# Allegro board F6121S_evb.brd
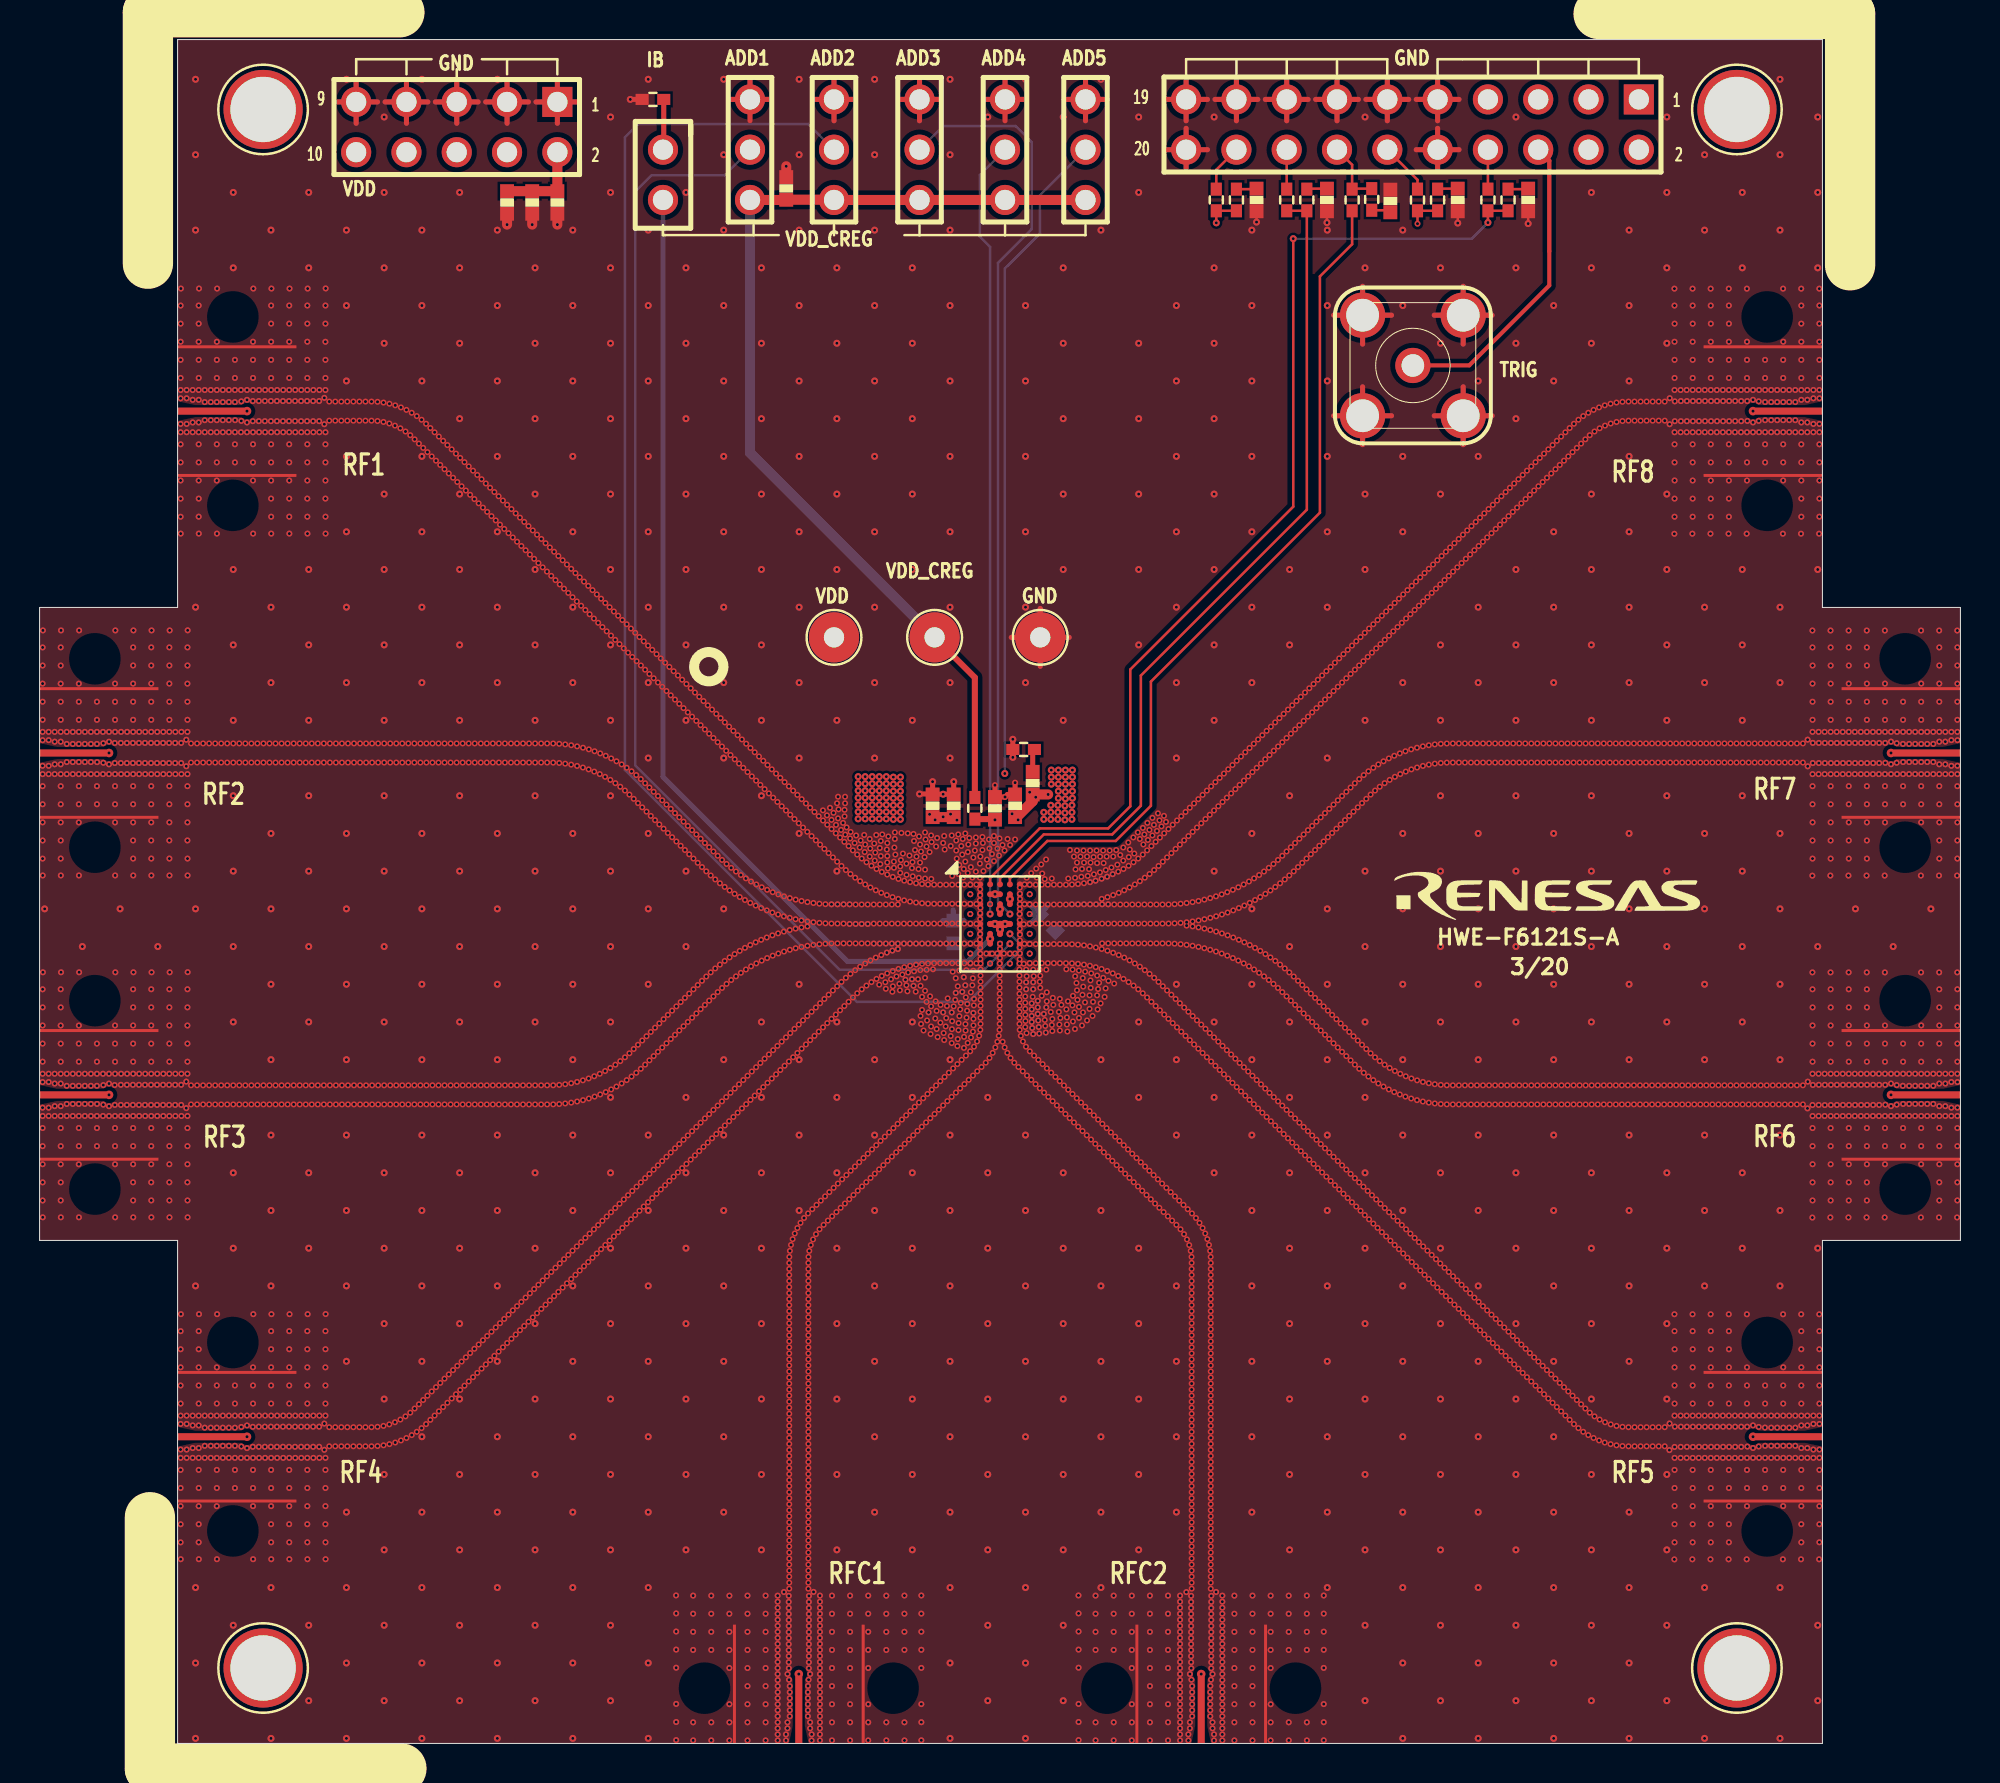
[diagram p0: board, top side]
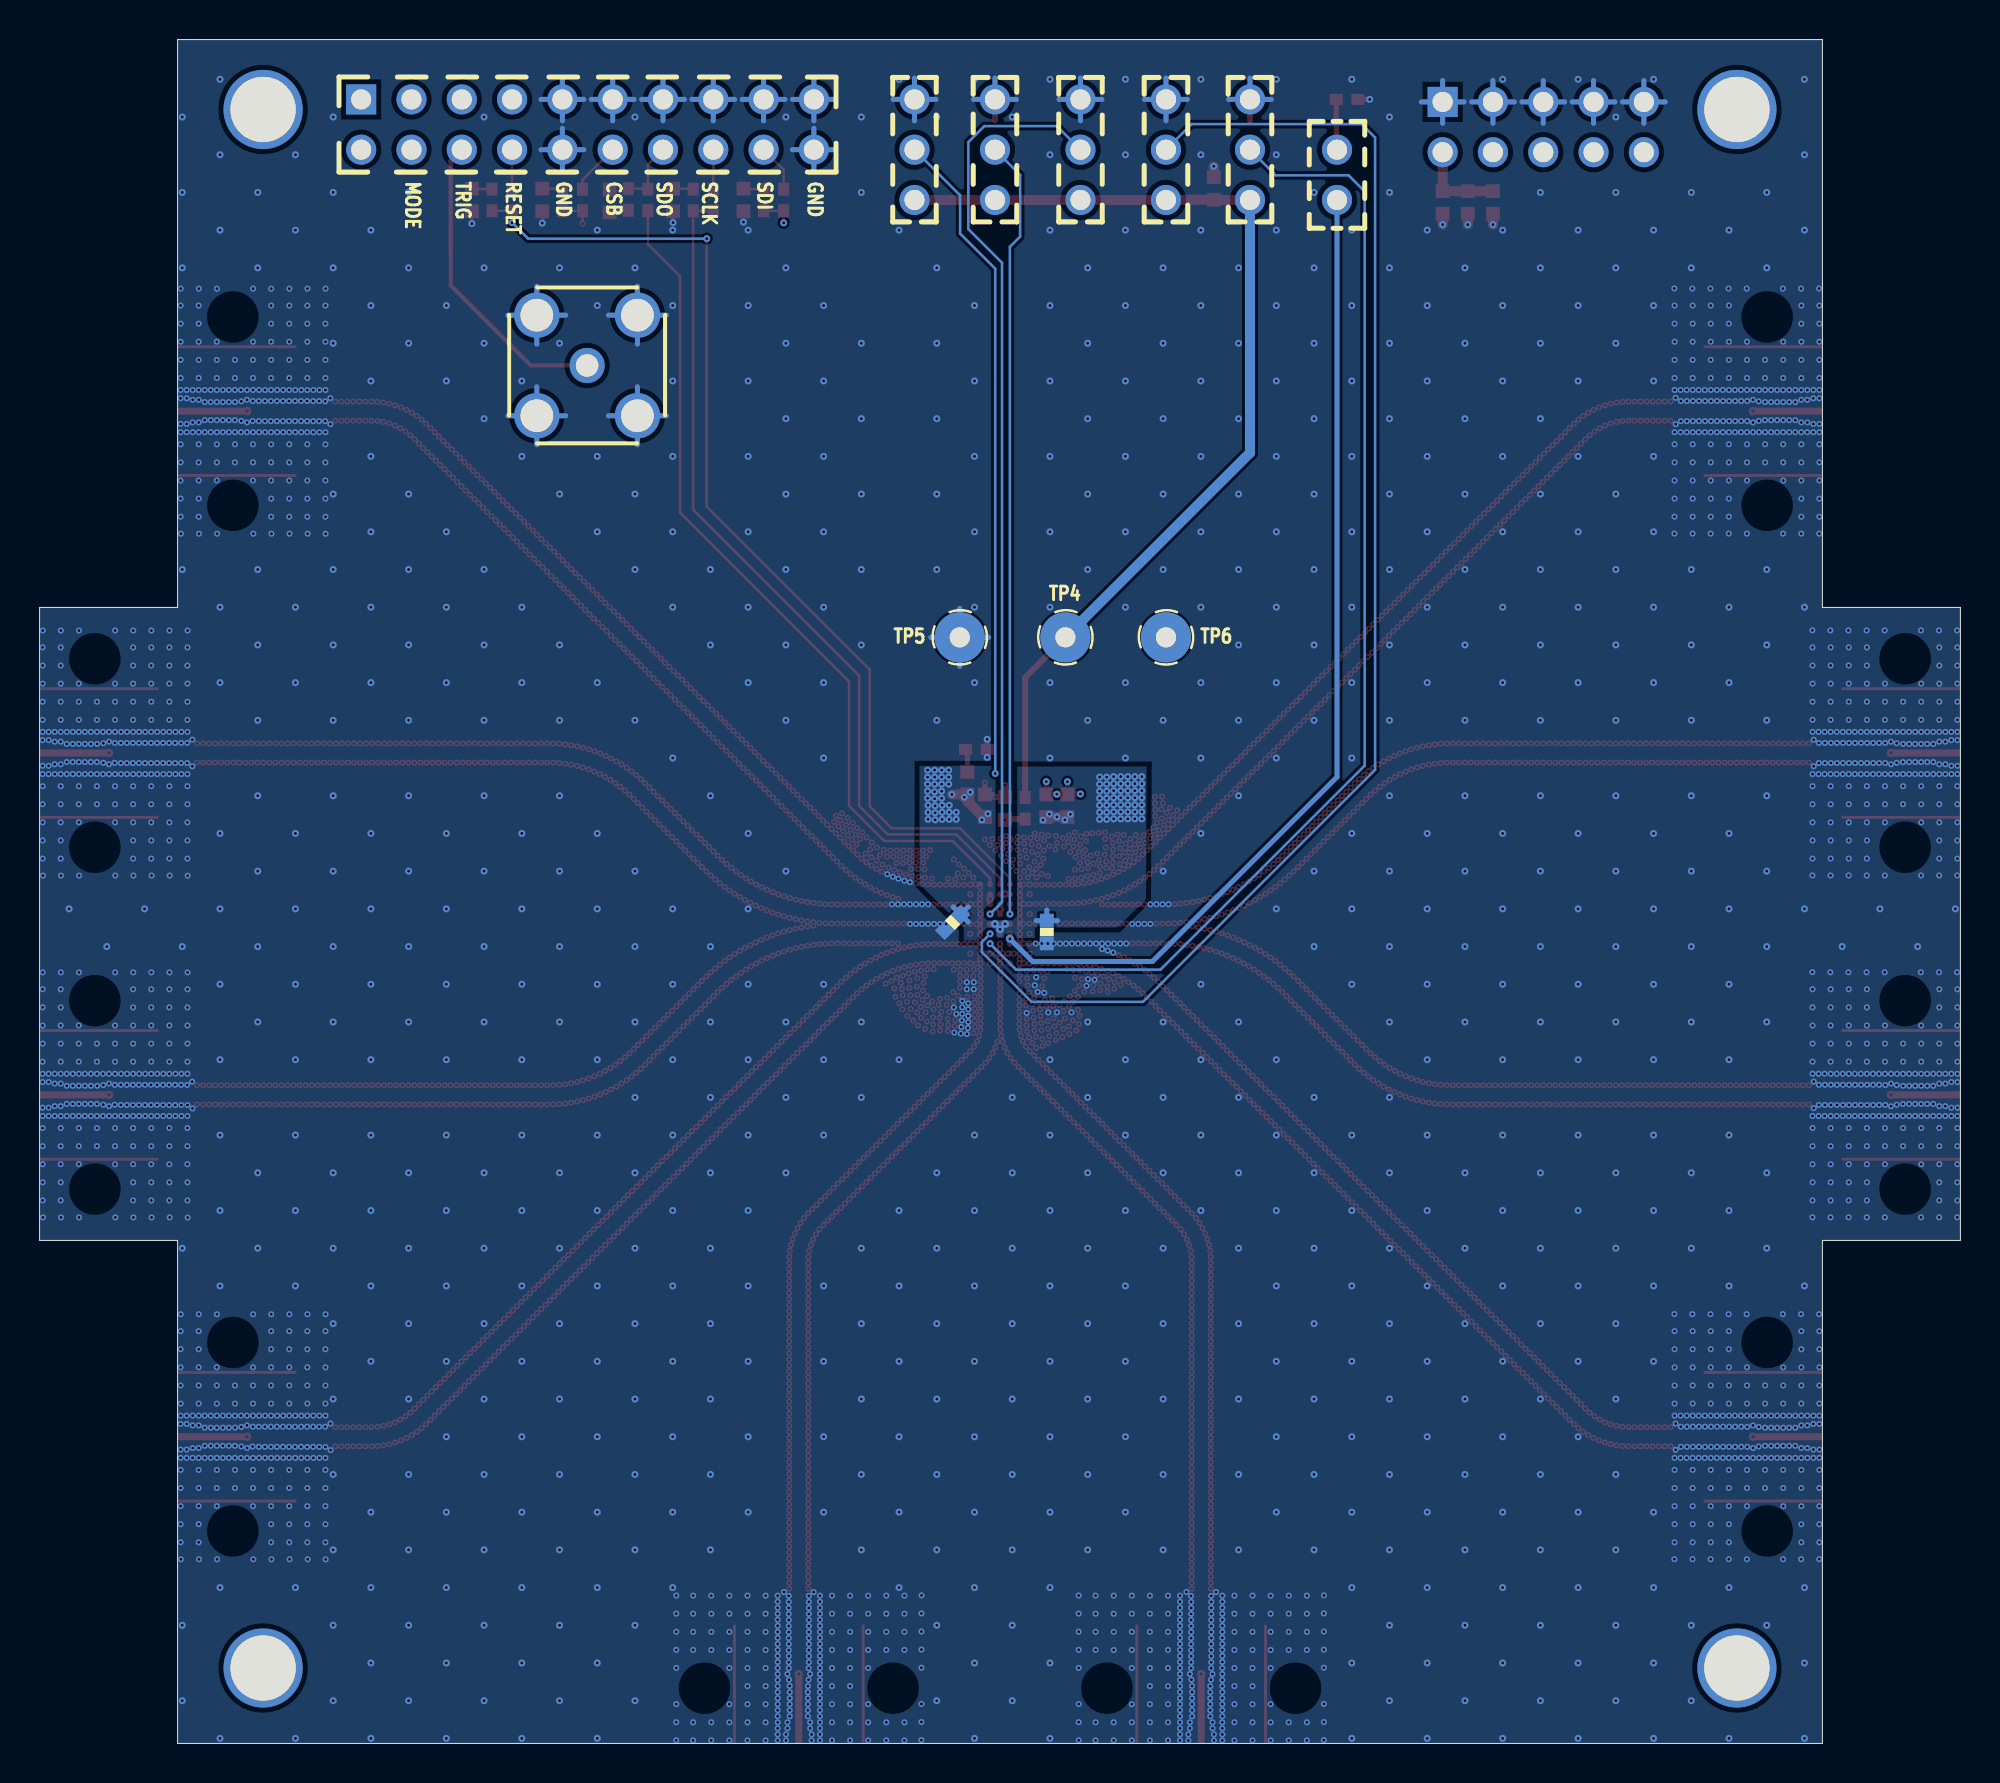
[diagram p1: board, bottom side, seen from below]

Outline 96.99 x 86.08 mm; copper layers: TOP, L2, L3, BOTTOM. Coordinates in mm from the lower left corner of the outline.
Outline path: 0,57.39 0,25.41 6.97,25.41 6.97,0 90.03,0 90.03,25.41 96.99,25.41 96.99,57.39 90.03,57.39 90.03,86.08 6.97,86.08 6.97,57.39 0,57.39

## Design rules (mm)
constraint set DEFAULT: min track width 0.127

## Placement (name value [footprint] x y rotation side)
C1  10uF  [CAPC1005N]  26.14 77.85 90 top
C3  DNI_C0402  [CAPC1005N]  23.6 77.85 90 top
C4  1uF  [CAPC1005N]  24.87 77.85 90 top
C5  100pF  [CAPC1005N]  46.16 47.37 270 top
C6  100pF  [CAPC1005N]  49.26 47.37 270 top
C7  0.1uF  [CAPC1005N]  45.09 47.37 270 top
C8  1uF  [CAPC1005N]  37.7 78.56 270 top
C9  1uF  [CAPC1005N]  48.24 47.24 90 top
C12  DNI_C0402  [CAPC1005N]  75.17 77.98 90 top
C14  DNI_C0402  [CAPC1005N]  71.61 77.98 90 top
C15  DNI_C0402  [CAPC1005N]  65.01 77.98 90 top
C16  DNI_C0402  [CAPC1005N]  61.45 77.98 90 top
C17  DNI_C0402  [CAPC1005N]  68.21 77.93 270 top
C18  0.018uF  [CAPC1005N]  50.88 41.48 135 bottom
C19  3900pF  [CAPC1005N]  46.13 41 90 bottom
C20  0.068uF  [CAPC1005N]  50.15 48.51 270 top
FID1  Fiducial  [FIDUCIAL]  91.42 87.38 0 top
FID2  Fiducial  [FIDUCIAL]  5.57 -1.27 180 top
FID3  Fiducial  [FIDUCIAL]  5.47 87.46 90 top
J1  ELF40-002 F6212  [ELF40-002_F6121]  6.97 67.31 270 top
J2  ELF40-002 F6212  [ELF40-002_F6121]  0 50.04 270 top
J3  ELF40-002 F6212  [ELF40-002_F6121]  0 32.77 270 top
J4  ELF40-002 F6212  [ELF40-002_F6121]  6.97 15.49 270 top
J5  ELF40-002 F6212  [ELF40-002_F6121]  38.34 0 0 top
J10  ELF40-002 F6212  [ELF40-002_F6121]  58.66 0 0 top
J11  Headerstrip 1X3  [HEADER_1X3_VERTICAL]  35.87 80.52 270 top
J12  Headerstrip 1X3  [HEADER_1X3_VERTICAL]  40.11 80.52 90 top
J13  Headerstrip 1X3  [HEADER_1X3_VERTICAL]  44.43 80.52 90 top
J14  Headerstrip 1X3  [HEADER_1X3_VERTICAL]  48.75 80.52 90 top
J15  Headerstrip 1X3  [HEADER_1X3_VERTICAL]  52.81 80.52 270 top
J16  Headerstrip 2X5  [HEADER_2X5]  21.06 81.66 180 top
J17  ELF40-002 F6212  [ELF40-002_F6121]  90.03 15.49 90 top
J18  ELF40-002 F6212  [ELF40-002_F6121]  96.99 32.77 90 top
J19  ELF40-002 F6212  [ELF40-002_F6121]  96.99 50.04 90 top
J20  ELF40-002 F6212  [ELF40-002_F6121]  90.03 67.31 90 top
J22  Headerstrip 2X10  [HEADER_2X10]  69.32 81.79 180 top
J23  Headerstrip 1X2  [HEADER_1X2_VERTICAL]  31.48 79.25 270 top
J30  TE: 1-1337482-0  [SMA_VERT_SNAP_ON-5]  69.35 69.62 0 top
NOREF  -  []  68.05 41.4 0 top
NOREF#2  -  []  -216.17 -221.64 0 top
NOREF#3  -  []  6.97 0 90 top
NOREF#4  -  []  6.97 86.08 0 top
R10  0.00  [RESC1005N]  73.13 77.98 270 top
R11  DNI_R0402  [RESC1005N]  74.15 77.98 270 top
R12  0.00  [RESC1005N]  69.58 77.98 270 top
R13  DNI_R0402  [RESC1005N]  70.59 77.98 270 top
R14  0.00  [RESC1005N]  62.97 77.98 270 top
R15  DNI_R0402  [RESC1005N]  63.99 77.98 270 top
R16  0.00  [RESC1005N]  59.42 77.98 270 top
R17  DNI_R0402  [RESC1005N]  60.43 77.98 270 top
R18  0.00  [RESC1005N]  66.28 77.98 270 top
R19  DNI_R0402  [RESC1005N]  67.27 78 90 top
R20  DNI_R0402  [RESC1005N]  47.23 47.24 90 top
R21  DNI_R0402  [RESC1005N]  30.97 83.06 180 top
R26  0.00  [RESC1005N]  49.69 50.22 0 top
SO1  Standoff 25mm  [MH320]  11.29 82.55 0 top
SO2  Standoff 25mm  [MH320]  85.71 82.55 0 top
SO3  Standoff 25mm  [MH320]  11.29 3.81 0 top
SO4  Standoff 25mm  [MH320]  85.71 3.81 0 top
TP4  Loop  [TP254_102]  45.19 55.88 0 top
TP5  Loop  [TP254_102]  50.53 55.88 0 top
TP6  Loop  [TP254_102]  40.11 55.88 0 top
U3  F6121S  [BGA63_50P_3X4]  48.5 41.4 0 top

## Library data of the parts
C1 C3-C9 C12 C14-C20 = CAP_1005N: alternate symbols: (CAPC1005L,CAPC1005RF)
FID1-FID3 = Fiducial
J1-J5 J10 J17-J20 = SMA_EDGE_ELF40
J11-J15 = HEADER_1X3
J16 = HEADER_2X5
J22 = HEADER_2X10
J23 = header_1x2
J30 = SMA_VERT_SNAPON
R10-R21 R26 = RESISTOR_1005N: alternate symbols: (RESC1005RF,RESC1005L,RESC1005M)
SO1-SO4 = Standoff
TP4-TP6 = TESTPOINT
U3 = F6121S

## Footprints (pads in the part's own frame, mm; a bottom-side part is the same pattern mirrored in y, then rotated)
BGA63_50P_3X4
  round 0.3 smd: A1(-1.5,2) A2(-1,2) A3(-0.5,2) A4(0,2) A5(0.5,2) A6(1,2) A7(1.5,2) B1(-1.5,1.5) B2(-1,1.5) B3(-0.5,1.5) B4(0,1.5) B5(0.5,1.5) B6(1,1.5) B7(1.5,1.5) C1(-1.5,1) C2(-1,1) C3(-0.5,1) C4(0,1) C5(0.5,1) C6(1,1) C7(1.5,1) D1(-1.5,0.5) D2(-1,0.5) D3(-0.5,0.5) D4(0,0.5) D5(0.5,0.5) D6(1,0.5) D7(1.5,0.5) E1(-1.5,0) E2(-1,0) E3(-0.5,0) E4(0,0) E5(0.5,0) E6(1,0) E7(1.5,0) F1(-1.5,-0.5) F2(-1,-0.5) F3(-0.5,-0.5) F4(0,-0.5) F5(0.5,-0.5) F6(1,-0.5) F7(1.5,-0.5) G1(-1.5,-1) G2(-1,-1) G3(-0.5,-1) G4(0,-1) G5(0.5,-1) G6(1,-1) G7(1.5,-1) H1(-1.5,-1.5) H2(-1,-1.5) H3(-0.5,-1.5) H4(0,-1.5) H5(0.5,-1.5) H6(1,-1.5) H7(1.5,-1.5) J1(-1.5,-2) J2(-1,-2) J3(-0.5,-2) J4(0,-2) J5(0.5,-2) J6(1,-2) J7(1.5,-2)
CAPC1005N
  rect 0.7x0.7 smd: 1(-0.572,0) 2(0.572,0)
ELF40-002_F6121
  round 0 hole 2.032 unplated: (-4.76,2.79) (4.76,2.79)
  rect 0.15x2.54 smd: 1(0,1.27)
  rect 0.15x6 smd: 2(3.25,3) 3(-3.25,3)
HEADER_1X2_VERTICAL
  round 1.52 hole 1.02: 1(-1.27,0) 2(1.27,0)
HEADER_1X3_VERTICAL
  round 1.52 hole 1.02: 1(-2.54,0) 2(0,0) 3(2.54,0)
HEADER_2X5
  rect 1.52x1.52 hole 1.02: 1(-5.08,-1.27)
  round 1.52 hole 1.02: 2(-5.08,1.27) 3(-2.54,-1.27) 4(-2.54,1.27) 5(0,-1.27) 6(0,1.27) 7(2.54,-1.27) 8(2.54,1.27) 9(5.08,-1.27) 10(5.08,1.27)
HEADER_2X10
  rect 1.52x1.52 hole 1.02: 1(-11.43,-1.27)
  round 1.52 hole 1.02: 2(-11.43,1.27) 3(-8.89,-1.27) 4(-8.89,1.27) 5(-6.35,-1.27) 6(-6.35,1.27) 7(-3.81,-1.27) 8(-3.81,1.27) 9(-1.27,-1.27) 10(-1.27,1.27) 11(1.27,-1.27) 12(1.27,1.27) 13(3.81,-1.27) 14(3.81,1.27) 15(6.35,-1.27) 16(6.35,1.27) 17(8.89,-1.27) 18(8.89,1.27) 19(11.43,-1.27) 20(11.43,1.27)
MH320
  round 4 hole 3.3: (0,0)
RESC1005N
  rect 0.66x0.56 smd: 1(-0.546,0) 2(0.546,0)
SMA_VERT_SNAP_ON-5
  round 1.778 hole 1.143: 1(0,0)
  round 2.286 hole 1.651: 2(-2.54,2.54) 3(2.54,2.54) 4(2.54,-2.54) 5(-2.54,-2.54)
TP254_102
  round 2.54 hole 1.02: 1(0,0)

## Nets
GND: C1.1 C3.1 C4.1 C5.1 C6.1 C7.1 C8.1 C9.2(B) C12.1 C14.1 C15.1 C16.1 C17.1 C18.1 C19.1 J1.2 J1.3 J2.2 J2.3 J3.2 J3.3 J4.2 J4.3 J5.2 J5.3 J10.2 J10.3 J11.1 J12.3 J13.3 J14.3 J15.1 J16.1 J16.3 J16.5 J16.7 J16.9 J17.2 J17.3 J18.2 J18.3 J19.2 J19.3 J20.2 J20.3 J22.9 J22.10 J22.11 J22.13 J22.15 J22.17 J22.19 J22.20 J30.2 J30.3 J30.4 J30.5 R21.2 R26.1 TP5.1 U3.A1 U3.A2 U3.A6 U3.A7 U3.B2 U3.B6 U3.C1 U3.C2 U3.C6 U3.C7 U3.D2 U3.D6 U3.E1 U3.E2 U3.E6 U3.E7 U3.F2 U3.F6 U3.G1 U3.G2 U3.G4 U3.G6 U3.G7 U3.H2 U3.H3 U3.H4 U3.H5 U3.H6 U3.J1 U3.J2 U3.J4 U3.J6 U3.J7
VDD: C1.2(B) C3.2(B) C4.2(B) C5.2(B) C6.2(B) C7.2(B) C18.2(B) C19.2(B) C20.2(B) J16.2 J16.4 J16.6 J16.8 J16.10 TP6.1 U3.E3 U3.E4 U3.E5 U3.F4(VDD_F4)
VDD_CREG: C8.2(B) J11.3 J12.1 J13.1 J14.1 J15.3 R20.2 TP4.1
ADD1: J11.2 U3.G5
ADD2: J12.2 U3.F5
ADD3: J13.2 U3.D5
ADD4: J14.2 U3.D3
ADD5: J15.2 U3.C3
CREG: C9.1 R20.1 U3.C4 U3.D4
CSB: R12.2 R13.2 U3.B3 U3.B4
F2232H_CSB: J22.12 R12.1
F2232H_RESET: J22.8 R10.1
F2232H_SCLK: J22.16 R14.1
RESET: R10.2 R11.2 U3.A3
RF1: J1.1 U3.B1
RF2: J2.1 U3.D1
RF3: J3.1 U3.F1
RF4: J4.1 U3.H1
RF5: J17.1 U3.H7
RF6: J18.1 U3.F7
RF7: J19.1 U3.D7
RF8: J20.1 U3.B7
SCLK: R14.2 R15.2 U3.A4
SDI: R16.2 R17.2 U3.B5 U3.C5
SDO: R18.2 U3.A5
TRIG: J22.6 J30.1(S1)
N397655: J10.1 U3.J5
N397670: J5.1 U3.J3
N472884: C12.2(B) R11.1
N475952: J22.18 R16.1
N485360: J22.14 R18.1 R19.2
N489259: J23.1 R21.1
N510107: C14.2(B) R13.1
N511327: C17.2(B) R19.1
N512531: C15.2(B) R15.1
N513256: C16.2(B) R17.1
N546379: J23.2 U3.F3 U3.G3
N558773: C20.1 R26.2

Pads without a net: J22 1 2 3 4 5 7

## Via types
v1: diameter 0.305, hole 0.152, TOP to L2, 387 vias
v2: diameter 0.406, hole 0.152, TOP to BOTTOM, 4 vias
v3: diameter 0.305, hole 0.152, TOP to L3, 2573 vias
v4: diameter 0.406, hole 0.152, TOP to L3, 1 via
v5: diameter 0.406, hole 0.152, TOP to L2, 2 vias
v6: diameter 0.356, hole 0.152, TOP to BOTTOM, 829 vias
v7: diameter 0.305, hole 0.152, TOP to BOTTOM, 2008 vias

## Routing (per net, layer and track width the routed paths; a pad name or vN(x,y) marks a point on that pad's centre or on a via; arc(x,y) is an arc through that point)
GND: length 429.3
  TOP w0.127: C12.1 v6(75.17,76.78) ; 45.11,47.96 C7.1 ; C14.1 v6(71.61,76.81) ; C16.1 v6(61.45,76.86) ; C15.1 v6(65.01,76.84)
  TOP w0.254: 21.06,81.85 J16.5 ; J16.5 19.99,82.93 ; J16.5 22.14,82.93 ; J16.5 21.06,84.01 ; 60.43,81.98 J22.17 ; J22.17 60.43,84.14 ; J22.17 59.36,83.06 ; J22.17 61.51,83.06 ; TP5.1 50.53,57.34 ; TP5.1 51.99,55.88 ; TP5.1 49.07,55.88 ; TP5.1 50.53,54.42 ; J22.19 58.97,83.06 ; J22.19 57.89,84.14 ; J22.19 56.82,83.06 ; J22.19 57.89,81.98 ; J30.4 73.35,67.08 ; J30.4 70.43,67.08 ; J30.4 71.89,68.54 ; J30.4 71.89,65.62 ; 70.43,72.16 J30.3 ; J30.3 71.89,73.62 ; J30.3 71.89,70.7 ; J30.3 73.35,72.16 ; 44.43,81.98 J13.3 ; J13.3 43.35,83.06 ; J13.3 44.43,84.14 ; J13.3 45.51,83.06 ; v3(48.24,48.41) C9.2 v3(48.75,47.82) 48.88,47.94 C6.1 v3(49.26,48.54) ; J22.11 69.13,83.06 ; J22.11 66.98,83.06 ; J22.11 68.05,84.14 ; J22.11 68.05,81.98 ; J11.1 35.87,84.14 ; J11.1 36.95,83.06 ; J11.1 34.79,83.06 ; J11.1 35.87,81.98 ; 25.07,82.93 J16.1 ; J16.1 26.14,81.85 ; J16.1 26.14,84.01 ; J16.1 27.22,82.93 ; 66.81,70.7 J30.2 ; J30.2 68.27,72.16 ; J30.2 65.35,72.16 ; J30.2 66.81,73.62 ; J16.3 24.68,82.93 ; J16.3 22.53,82.93 ; J16.3 23.6,81.85 ; J16.3 23.6,84.01 ; J14.3 48.75,84.14 ; J14.3 47.67,83.06 ; J14.3 49.83,83.06 ; J14.3 48.75,81.98 ; J22.13 66.59,83.06 ; J22.13 65.51,81.98 ; J22.13 65.51,84.14 ; J22.13 64.44,83.06 ; 14.91,82.93 J16.9 ; J16.9 15.98,84.01 ; J16.9 15.98,81.85 ; J16.9 17.06,82.93 ; J12.3 40.11,84.14 ; J12.3 39.04,83.06 ; J12.3 40.11,81.98 ; J12.3 41.19,83.06 ; J15.1 52.81,84.14 ; J15.1 53.89,83.06 ; J15.1 52.81,81.98 ; J15.1 51.74,83.06 ; 69.52,80.52 J22.10 ; J22.10 71.67,80.52 ; J22.10 70.59,81.6 ; J22.10 70.59,79.44 ; J16.7 19.6,82.93 ; J16.7 18.52,84.01 ; J16.7 18.52,81.85 ; J16.7 17.45,82.93 ; J22.9 70.59,84.14 ; J22.9 69.52,83.06 ; J22.9 71.67,83.06 ; J22.9 70.59,81.98 ; R21.2 v6(29.83,83.06) ; 56.82,80.52 J22.20 ; J22.20 58.97,80.52 ; J22.20 57.89,79.44 ; J22.20 57.89,81.6 ; v6(49.14,49.82) R26.1 v6(49.14,50.73) ; 45.11,47.96 v6(45.63,47.96) 46.15,47.96 C5.1 v6(46.16,48.59) ; J30.5 68.27,67.08 ; J30.5 66.81,65.62 ; J30.5 66.81,68.54 ; J30.5 65.35,67.08 ; 61.9,83.06 J22.15 ; J22.15 64.05,83.06 ; J22.15 62.97,84.14 ; J22.15 62.97,81.98 ; v6(45.09,48.59) C7.1 45.07,47.97 v6(44.43,47.97)
  TOP w0.508: C1.1 v6(26.14,76.73) ; C3.1 v6(23.6,76.73) ; C4.1 v6(24.87,76.73) ; C8.1 v6(37.7,79.68)
  L2 w0.254: 40.11,81.98 J12.3 ; J12.3 40.11,84.14 ; J12.3 39.04,83.06 ; J12.3 41.19,83.06 ; 68.05,81.98 J22.11 ; J22.11 66.98,83.06 ; J22.11 69.13,83.06 ; J22.11 68.05,84.14 ; 57.89,79.44 J22.20 ; J22.20 58.97,80.52 ; J22.20 56.82,80.52 ; J22.20 57.89,81.6 ; 70.43,67.08 J30.4 ; J30.4 71.89,65.62 ; J30.4 71.89,68.54 ; J30.4 73.35,67.08 ; 34.79,83.06 J11.1 ; J11.1 36.95,83.06 ; J11.1 35.87,81.98 ; J11.1 35.87,84.14 ; 52.81,81.98 J15.1 ; J15.1 51.74,83.06 ; J15.1 52.81,84.14 ; J15.1 53.89,83.06 ; 65.35,67.08 J30.5 ; J30.5 66.81,68.54 ; J30.5 68.27,67.08 ; J30.5 66.81,65.62 ; J13.3 44.43,84.14 ; J13.3 43.35,83.06 ; J13.3 44.43,81.98 ; J13.3 45.51,83.06 ; J22.10 71.67,80.52 ; J22.10 70.59,81.6 ; J22.10 70.59,79.44 ; J22.10 69.52,80.52 ; J22.13 65.51,84.14 ; J22.13 66.59,83.06 ; J22.13 64.44,83.06 ; J22.13 65.51,81.98 ; 57.89,81.98 J22.19 ; J22.19 56.82,83.06 ; J22.19 58.97,83.06 ; J22.19 57.89,84.14 ; J16.9 17.06,82.93 ; J16.9 14.91,82.93 ; J16.9 15.98,84.01 ; J16.7 18.52,84.01 ; J16.7 19.6,82.93 ; J16.7 17.45,82.93 ; J16.5 22.14,82.93 ; J16.5 21.06,84.01 ; J16.5 19.99,82.93 ; J30.3 73.35,72.16 ; J30.3 70.43,72.16 ; J30.3 71.89,70.7 ; J30.3 71.89,73.62 ; J14.3 49.83,83.06 ; J14.3 48.75,81.98 ; J14.3 48.75,84.14 ; J14.3 47.67,83.06 ; 65.35,72.16 J30.2 ; J30.2 66.81,73.62 ; J30.2 66.81,70.7 ; J30.2 68.27,72.16 ; TP5.1 50.53,57.07 ; TP5.1 49.34,55.88 ; TP5.1 51.72,55.88 ; TP5.1 50.53,54.69 ; J22.17 61.51,83.06 ; J22.17 60.43,84.14 ; J22.17 59.36,83.06 ; J22.17 60.43,81.98 ; 70.59,81.98 J22.9 ; J22.9 70.59,84.14 ; J22.9 71.67,83.06 ; J22.9 69.52,83.06 ; 61.9,83.06 J22.15 ; J22.15 62.97,81.98 ; J22.15 64.05,83.06 ; J22.15 62.97,84.14 ; J16.3 23.6,84.01 ; J16.3 24.68,82.93 ; J16.3 22.53,82.93 ; J16.1 26.14,84.01 ; J16.1 27.22,82.93 ; J16.1 25.07,82.93
  L3 w0.254: J22.13 65.51,84.14 ; J22.13 64.44,83.06 ; J22.13 65.51,81.98 ; J22.13 66.59,83.06 ; J16.1 27.22,82.93 ; J16.1 26.14,84.01 ; J16.1 26.14,81.85 ; J16.1 25.07,82.93 ; J30.3 71.89,73.62 ; J30.3 71.89,70.7 ; J30.3 70.43,72.16 ; J30.3 73.35,72.16 ; J16.9 15.98,84.01 ; J16.9 15.98,81.85 ; J16.9 14.91,82.93 ; J16.9 17.06,82.93 ; 62.97,81.98 J22.15 ; J22.15 61.9,83.06 ; J22.15 62.97,84.14 ; J22.15 64.05,83.06 ; 49.34,55.88 TP5.1 ; TP5.1 50.53,57.07 ; TP5.1 50.53,54.69 ; TP5.1 51.72,55.88 ; 52.81,81.98 J15.1 ; J15.1 52.81,84.14 ; J15.1 51.74,83.06 ; J15.1 53.89,83.06 ; J30.5 68.27,67.08 ; J30.5 65.35,67.08 ; J30.5 66.81,65.62 ; J30.5 66.81,68.54 ; 17.45,82.93 J16.7 ; J16.7 19.6,82.93 ; J16.7 18.52,84.01 ; J16.7 18.52,81.85 ; J22.20 58.97,80.52 ; J22.20 57.89,79.44 ; J22.20 56.82,80.52 ; J22.20 57.89,81.6 ; J14.3 48.75,84.14 ; J14.3 49.83,83.06 ; J14.3 48.75,81.98 ; J14.3 47.67,83.06 ; 44.43,81.98 J13.3 ; J13.3 45.51,83.06 ; J13.3 43.35,83.06 ; J13.3 44.43,84.14 ; J22.19 58.97,83.06 ; J22.19 57.89,84.14 ; J22.19 57.89,81.98 ; J22.19 56.82,83.06 ; J12.3 40.11,84.14 ; J12.3 41.19,83.06 ; J12.3 39.04,83.06 ; J12.3 40.11,81.98 ; 65.35,72.16 J30.2 ; J30.2 68.27,72.16 ; J30.2 66.81,70.7 ; J30.2 66.81,73.62 ; 19.99,82.93 J16.5 ; J16.5 21.06,84.01 ; J16.5 22.14,82.93 ; J16.5 21.06,81.85 ; J22.17 61.51,83.06 ; J22.17 60.43,81.98 ; J22.17 59.36,83.06 ; J22.17 60.43,84.14 ; J22.10 71.67,80.52 ; J22.10 69.52,80.52 ; J22.10 70.59,79.44 ; J22.10 70.59,81.6 ; J16.3 23.6,84.01 ; J16.3 24.68,82.93 ; J16.3 22.53,82.93 ; J16.3 23.6,81.85 ; 70.43,67.08 J30.4 ; J30.4 71.89,68.54 ; J30.4 73.35,67.08 ; J30.4 71.89,65.62 ; 35.87,81.98 J11.1 ; J11.1 34.79,83.06 ; J11.1 35.87,84.14 ; J11.1 36.95,83.06 ; J22.9 70.59,84.14 ; J22.9 71.67,83.06 ; J22.9 70.59,81.98 ; J22.9 69.52,83.06 ; 66.98,83.06 J22.11 ; J22.11 68.05,81.98 ; J22.11 68.05,84.14 ; J22.11 69.13,83.06
  BOTTOM w0.254: 49.07,55.88 TP5.1 ; TP5.1 50.53,57.34 ; TP5.1 51.99,55.88 ; TP5.1 50.53,54.42 ; 59.36,83.06 J22.17 ; J22.17 61.51,83.06 ; J22.17 60.43,84.14 ; J22.17 60.43,81.98 ; 51.74,83.06 J15.1 ; J15.1 53.89,83.06 ; J15.1 52.81,84.14 ; J15.1 52.81,81.98 ; J30.5 66.81,68.54 ; J30.5 68.27,67.08 ; J30.5 66.81,65.62 ; J30.5 65.35,67.08 ; J22.9 70.59,84.14 ; J22.9 70.59,81.98 ; J22.9 71.67,83.06 ; J22.9 69.52,83.06 ; J12.3 40.11,84.14 ; J12.3 41.19,83.06 ; J12.3 40.11,81.98 ; J12.3 39.04,83.06 ; J16.7 18.52,84.01 ; J16.7 17.45,82.93 ; J16.7 18.52,81.85 ; J16.7 19.6,82.93 ; 61.9,83.06 J22.15 ; J22.15 62.97,81.98 ; J22.15 62.97,84.14 ; J22.15 64.05,83.06 ; J16.5 21.06,84.01 ; J16.5 22.14,82.93 ; J16.5 19.99,82.93 ; J16.5 21.06,81.85 ; 57.89,79.44 J22.20 ; J22.20 57.89,81.6 ; J22.20 58.97,80.52 ; J22.20 56.82,80.52 ; 70.43,67.08 J30.4 ; J30.4 71.89,65.62 ; J30.4 71.89,68.54 ; J30.4 73.35,67.08 ; J16.9 15.98,84.01 ; J16.9 14.91,82.93 ; J16.9 17.06,82.93 ; J16.9 15.98,81.85 ; 56.82,83.06 J22.19 ; J22.19 57.89,84.14 ; J22.19 58.97,83.06 ; J22.19 57.89,81.98 ; J11.1 36.95,83.06 ; J11.1 35.87,84.14 ; J11.1 34.79,83.06 ; 70.43,72.16 J30.3 ; J30.3 71.89,73.62 ; J30.3 71.89,70.7 ; J30.3 73.35,72.16 ; J22.11 68.05,84.14 ; J22.11 66.98,83.06 ; J22.11 68.05,81.98 ; J22.11 69.13,83.06 ; J22.10 70.59,81.6 ; J22.10 69.52,80.52 ; J22.10 70.59,79.44 ; J22.10 71.67,80.52 ; J13.3 44.43,84.14 ; J13.3 44.43,81.98 ; J13.3 43.35,83.06 ; J13.3 45.51,83.06 ; 47.67,83.06 J14.3 ; J14.3 48.75,84.14 ; J14.3 49.83,83.06 ; J16.3 23.6,84.01 ; J16.3 22.53,82.93 ; J16.3 23.6,81.85 ; J16.3 24.68,82.93 ; J30.2 68.27,72.16 ; J30.2 65.35,72.16 ; J30.2 66.81,73.62 ; J30.2 66.81,70.7 ; 25.07,82.93 J16.1 ; J16.1 26.14,81.85 ; J16.1 26.14,84.01 ; J16.1 27.22,82.93 ; 64.44,83.06 J22.13 ; J22.13 65.51,84.14 ; J22.13 66.59,83.06 ; J22.13 65.51,81.98
  vias: v1(39.56,47.14) v1(39.76,46.89) v1(39.91,47.27) v1(39.99,46.66) v1(40.09,47.02) v1(40.22,46.41) v1(40.32,47.83) v1(40.27,47.5) v1(40.34,47.19) v1(40.32,46.74) v1(40.47,46.15) v1(40.57,46.51) v1(40.67,47.83) v1(40.67,47.5) v1(40.65,47.17) v1(40.65,46.84) v1(40.68,45.92) v1(40.75,46.28) v1(40.93,45.72) v1(40.95,46.05) v1(41.23,45.87) v1(41.16,45.49) v1(41.41,45.26) v1(41.46,45.62) v1(41.64,45.9) v1(41.69,45.42) v1(41.66,45.03) v1(41.92,45.69) v1(41.94,45.21) v1(41.92,44.81) v1(42.15,45.47) v1(42.2,45.01) v1(42.17,44.6) v1(42.25,45.9) v1(42.43,45.24) v1(42.4,38.33) v1(42.48,45.59) v1(42.48,44.83) v1(42.45,44.42) v1(42.55,45.92) v1(42.71,38.46) v1(42.73,38.13) v1(42.81,45.49) v1(42.78,45.16) v1(42.81,44.83) v1(42.8,44.51) v1(42.84,44.21) v1(42.86,45.82) v1(42.99,38.61) v1(43.14,44.55) v1(43.14,44.24) v1(43.09,38.25) v1(43.06,37.97) v1(43.19,46.02) v1(43.19,45.69) v1(43.16,45.26) v1(43.21,44.91) v1(43.27,38.75) v1(43.42,38.38) v1(43.44,38.05) v1(43.52,46) v1(43.49,44.63) v1(43.46,44.31) v1(43.46,43.98) v1(43.59,44.96) v1(43.57,38.84) v1(43.84,45.98) v1(43.77,44.45) v1(43.78,43.88) v1(43.77,38.3) v1(43.82,38) v1(43.92,44.86) v1(43.86,38.95) v1(44.13,45.95) v1(44.08,44.53) v1(44.05,44.22) v1(44.09,43.81) v1(44.15,45.59) v1(44.2,45.14) v1(44.16,39.01) v1(44.24,37.98) v1(44.28,44.81) v1(44.41,45.82) v1(44.38,44.17) v1(44.4,43.73) v1(44.36,38.61) v1(44.46,45.42) v1(44.51,45.06) v1(44.46,44.5) v1(44.47,39.07) v1(44.48,38.28) v1(44.48,36.75) v1(44.51,36.35) v1(44.56,37.72) v1(44.56,37.06) v1(44.64,36.02) v1(44.71,46.02) v1(44.74,45.67) v1(44.69,44.78) v1(44.71,44.15) v1(44.71,43.7) v1(44.71,38.68) v1(44.71,38.02) v1(44.79,45.31) v1(44.79,39.09) v1(44.79,37.47) v1(44.81,36.53) v1(44.94,45.03) v1(45.02,45.87) v1(45.04,45.54) v1(45.03,43.68) v1(44.97,37.74) v1(45.02,37.24) v1(45.02,36.22) v1(44.99,35.84) v1(45.11,39.11) v1(45.25,37.49) v1(45.23,36.63) v1(45.32,45.75) v1(45.27,45.31) v1(45.3,37.01) v1(45.3,36.09) v1(45.35,35.69) v1(45.49,37.31) v1(45.49,36.42) v1(45.63,45.49) v1(45.68,45.85) v1(45.7,45.16) v1(45.65,35.89) v1(45.68,35.53) v1(45.82,37.26) v1(45.78,36.65) v1(45.75,36.22) v1(45.86,37.64) v1(46.01,45.34) v1(46.01,35.74) v1(46.06,45.87) v1(46.08,43.82) v1(46.11,38.99) v1(46.08,36.49) v1(46.07,36.09) v1(46.06,35.38) v1(46.24,37.57) v1(46.15,37.24) v1(46.29,45.62) v1(46.29,45.11) v1(46.31,44.7) v1(46.26,38.66) v1(46.35,35.23) v1(46.39,45.92) v1(46.44,44.38) v1(46.39,43.92) v1(46.44,39.04) v1(46.36,38.25) v1(46.44,36.74) v1(46.41,36.39) v1(46.4,36.03) v1(46.36,35.59) v1(46.54,45.34) v1(46.52,37.41) v1(46.49,37.08) v1(46.62,45.69) v1(46.59,44.91) v1(46.64,43.75) v1(46.74,45.97) v1(46.74,44.55) v1(46.67,44.18) v1(46.68,35.7) v1(46.68,35.14) v1(46.79,39.07) v1(46.77,37.69) v1(46.85,37.36) v1(46.84,37.02) v1(46.81,36.67) v1(46.75,36.34) v1(46.76,36.02) v1(46.9,45.42) v1(46.87,45.03) v1(46.87,43.98) v1(46.87,35.39) v1(46.95,45.75) v1(47.02,44.27) v1(47.02,37.95) v1(47.03,35.67) v1(47.1,43.75) v1(47.13,38.66) v1(47.1,38.3) v1(47.13,35.96) v1(47.23,45.11) v1(47.15,44.75) v1(47.15,39.04) v1(47.18,37.61) v1(47.18,37.29) v1(47.16,36.61) v1(47.16,36.28) v1(47.28,45.77) v1(47.28,45.47) v1(47.28,44.04) v1(47.51,44.81) v1(47.48,44.45) v1(47.48,43.74) v1(47.61,45.8) v1(47.63,45.49) v1(47.61,45.14) v1(47.66,44.07) v1(47.84,44.65) v1(47.94,45.67) v1(47.91,44.32) v1(47.96,45.21) v1(48.09,44.93) v1(48.19,45.85) v1(48.19,45.49) v1(48.19,44.58) v1(48.37,45.21) v1(48.45,44.86) v1(48.47,45.72) v1(48.62,45.39) v1(48.73,45.11) v1(48.88,45.69) v1(49,45.39) v1(49.26,45.67) v1(49.84,43.74) v1(49.82,39.09) v1(49.84,38.76) v1(49.77,37.74) v1(49.77,37.42) v1(49.77,37.11) v1(49.78,36.81) v1(49.78,36.5) v1(49.77,36.19) v1(49.84,35.89) v1(50.07,43.97) v1(50.17,39.09) v1(50.2,38.76) v1(50.15,37.72) v1(50.33,44.2) v1(50.35,43.75) v1(50.5,39.09) v1(50.53,38.79) v1(50.5,38.48) v1(50.53,38.18) v1(50.58,44.41) v1(50.63,43.95) v1(50.6,37.77) v1(50.82,44.66) v1(50.75,43.67) v1(50.83,39.09) v1(50.76,36.55) v1(50.78,36.25) v1(50.86,37.95) v1(50.86,37.49) v1(51.11,43.7) v1(51.06,36.95) v1(51.14,36.6) v1(51.11,36.3) v1(51.14,35.99) v1(51.16,37.67) v1(51.19,37.31) v1(51.52,37.62) v1(51.47,36.96) v1(51.54,36.65) v1(51.49,36.32) v1(51.52,36.02) v1(51.6,37.31) v1(51.85,39.11) v1(51.94,43.7) v1(51.93,37.49) v1(51.85,37.08) v1(51.87,36.68) v1(51.87,36.32) v1(51.9,35.97) v1(52.03,45.14) v1(52.23,44.81) v1(52.16,39.1) v1(52.18,37.77) v1(52.15,37.29) v1(52.18,36.47) v1(52.31,44.16) v1(52.29,43.73) v1(52.29,38.76) v1(52.26,36.93) v1(52.28,36.09) v1(52.38,45.11) v1(52.38,44.5) v1(52.36,38.42) v1(52.38,38.05) v1(52.41,37.57) v1(52.48,39.05) v1(52.48,37.21) v1(52.48,36.65) v1(52.56,44.81) v1(52.64,44.18) v1(52.6,43.78) v1(52.64,36.27) v1(52.71,45.11) v1(52.74,44.5) v1(52.68,38.67) v1(52.7,38.23) v1(52.66,37.82) v1(52.69,36.93) v1(52.8,38.99) v1(52.79,37.44) v1(52.89,44.81) v1(52.93,43.83) v1(52.89,36.53) v1(53.04,45.11) v1(52.99,44.17) v1(53.02,37.8) v1(53.02,37.11) v1(53.07,44.5) v1(53.11,38.91) v1(53.07,38.55) v1(53.08,38.17) v1(53.22,44.78) v1(53.24,43.91) v1(53.2,37.47) v1(53.17,36.75) v1(53.37,45.11) v1(53.4,44.48) v1(53.4,38.8) v1(53.4,37.8) v1(53.42,37.08) v1(53.54,44.01) v1(53.5,38.43) v1(53.45,38.11) v1(53.55,44.81) v1(53.58,37.39) v1(53.7,45.11) v1(53.73,44.48) v1(53.71,38.68) v1(53.84,44.13) v1(53.83,38.15) v1(53.78,37.72) v1(53.88,44.81) v1(54.03,45.11) v1(53.97,38.52) v1(54.12,44.25) v1(54.21,44.81) v1(54.26,38.39) v1(54.36,45.14) v1(54.43,44.4) v1(54.57,44.88) v1(54.72,45.26) v1(54.72,44.6) v1(54.97,45.52) v1(55,44.78) v1(55.05,45.16) v1(55.23,45.77) v1(55.28,44.96) v1(55.46,46.02) v1(55.56,45.69) v1(55.71,46.25) v1(55.74,45.42) v1(55.79,45.92) v1(55.94,46.51) v1(56.04,46.15) v1(55.96,45.64) v1(56.19,46.76) v1(56.19,45.87) v1(56.27,46.41) v1(56.42,46.1) v1(56.47,46.99) v1(56.55,46.63) v1(56.65,46.33) v1(56.78,46.86) v1(56.88,46.56) v3(7.65,50.52) v3(7.65,49.56) v3(7.65,33.25) v3(7.65,32.28) v3(7.95,50.52) v3(7.95,49.56) v3(7.95,33.25) v3(7.95,32.28) v3(8.26,50.52) v3(8.26,49.56) v3(8.26,33.25) v3(8.26,32.28) v3(8.56,50.52) v3(8.56,49.56) v3(8.56,33.25) v3(8.56,32.28) v3(8.87,50.52) v3(8.87,49.56) v3(8.87,33.25) v3(8.87,32.28) v3(9.17,50.52) v3(9.17,49.56) v3(9.17,33.25) v3(9.17,32.28) v3(9.48,50.52) v3(9.48,49.56) v3(9.48,33.25) v3(9.48,32.28) v3(9.78,50.52) v3(9.78,49.56) v3(9.78,33.25) v3(9.78,32.28) v3(10.09,50.52) v3(10.09,49.56) v3(10.09,33.25) v3(10.09,32.28) v3(10.39,50.52) v3(10.39,49.56) v3(10.39,33.25) v3(10.39,32.28) v3(10.69,50.52) v3(10.69,49.56) v3(10.69,33.25) v3(10.69,32.28) v3(11,50.52) v3(11,49.56) v3(11,33.25) v3(11,32.28) v3(11.3,50.52) v3(11.3,49.56) v3(11.3,33.25) v3(11.3,32.28) v3(11.61,50.52) v3(11.61,49.56) v3(11.61,33.25) v3(11.61,32.28) v3(11.91,50.52) v3(11.91,49.56) v3(11.91,33.25) v3(11.91,32.28) v3(12.22,50.52) v3(12.22,49.56) v3(12.22,33.25) v3(12.22,32.28) v3(12.52,50.52) v3(12.52,49.56) v3(12.52,33.25) v3(12.52,32.28) v3(12.83,50.52) v3(12.83,49.56) v3(12.83,33.25) v3(12.83,32.28) v3(13.13,50.52) v3(13.13,49.56) v3(13.13,33.25) v3(13.13,32.28) v3(13.44,50.52) v3(13.44,49.56) v3(13.44,33.25) v3(13.44,32.28) v3(13.74,50.52) v3(13.74,49.56) v3(13.74,33.25) v3(13.74,32.28) v3(14.05,50.52) v3(14.05,49.56) v3(14.05,33.25) v3(14.05,32.28) v3(14.35,50.52) v3(14.35,49.56) v3(14.35,33.25) v3(14.35,32.28) v3(14.63,67.79) v3(14.63,66.83) v3(14.63,15.98) v3(14.63,15.01) v3(14.66,50.52) v3(14.66,49.56) v3(14.66,33.25) v3(14.66,32.28) v3(14.93,67.79) v3(14.93,66.83) v3(14.93,15.98) v3(14.93,15.01) v3(14.96,50.52) v3(14.96,49.56) v3(14.96,33.25) v3(14.96,32.28) v3(15.24,67.79) v3(15.24,66.83) v3(15.24,15.98) v3(15.24,15.01) v3(15.27,50.52) v3(15.27,49.56) v3(15.27,33.25) v3(15.27,32.28) v3(15.54,67.79) v3(15.54,66.83) v3(15.54,15.98) v3(15.54,15.01) v3(15.57,50.52) v3(15.57,49.56) v3(15.57,33.25) v3(15.57,32.28) v3(15.85,67.79) v3(15.84,66.83) v3(15.84,15.98) v3(15.85,15.01) v3(15.88,50.52) v3(15.88,49.56) v3(15.88,33.25) v3(15.88,32.28) v3(16.15,67.79) v3(16.15,66.83) v3(16.18,50.52) v3(16.18,49.56) v3(16.18,33.25) v3(16.18,32.28) v3(16.15,15.98) v3(16.15,15.01) v3(16.45,67.79) v3(16.45,66.83) v3(16.49,50.52) v3(16.49,49.56) v3(16.49,33.25) v3(16.49,32.28) v3(16.45,15.98) v3(16.45,15.01) v3(16.76,67.79) v3(16.76,66.83) v3(16.79,50.52) v3(16.79,49.56) v3(16.79,33.25) v3(16.79,32.28) v3(16.76,15.98) v3(16.76,15.01) v3(17.06,67.78) v3(17.06,66.81) v3(17.1,50.52) v3(17.1,49.56) v3(17.1,33.25) v3(17.1,32.28) v3(17.06,15.99) v3(17.06,15.02) v3(17.37,67.74) v3(17.36,66.76) v3(17.4,50.52) v3(17.4,49.56) v3(17.4,33.25) v3(17.4,32.28) v3(17.36,16.04) v3(17.37,15.06) v3(17.67,67.68) v3(17.66,66.68) v3(17.71,50.52) v3(17.71,49.56) v3(17.71,33.25) v3(17.71,32.28) v3(17.66,16.12) v3(17.67,15.12) v3(17.94,66.58) v3(17.94,16.23) v3(17.96,67.6) v3(18.01,50.52) v3(18.01,49.56) v3(18.01,33.25) v3(18.01,32.28) v3(17.96,15.2) v3(18.25,67.5) v3(18.22,66.44) v3(18.22,16.36) v3(18.25,15.31) v3(18.31,50.52) v3(18.31,49.56) v3(18.31,33.25) v3(18.31,32.28) v3(18.52,67.37) v3(18.48,66.28) v3(18.48,16.52) v3(18.52,15.43) v3(18.62,50.52) v3(18.62,49.56) v3(18.62,33.25) v3(18.62,32.28) v3(18.72,66.09) v3(18.72,16.71) v3(18.79,67.23) v3(18.79,15.58) v3(18.94,65.88) v3(18.92,50.52) v3(18.92,49.56) v3(18.92,33.25) v3(18.92,32.28) v3(18.94,16.92) v3(19.05,67.06) v3(19.05,15.74) v3(19.15,65.67) v3(19.23,50.52) v3(19.23,49.56) v3(19.23,33.25) v3(19.23,32.28) v3(19.15,17.14) v3(19.29,66.87) v3(19.29,15.93) v3(19.37,65.45) v3(19.37,17.35) v3(19.52,66.67) v3(19.53,50.52) v3(19.53,49.56) v3(19.53,33.25) v3(19.53,32.28) v3(19.52,16.13) v3(19.58,65.24) v3(19.58,17.57) v3(19.73,66.46) v3(19.73,16.35) v3(19.8,65.02) v3(19.84,50.52) v3(19.84,49.56) v3(19.84,33.25) v3(19.84,32.28) v3(19.8,17.78) v3(19.95,66.24) v3(19.95,16.56) v3(20.02,64.81) v3(20.02,18) v3(20.14,50.52) v3(20.14,49.56) v3(20.14,33.25) v3(20.14,32.28) v3(20.16,66.03) v3(20.23,64.59) v3(20.23,18.21) v3(20.16,16.78) v3(20.38,65.81) v3(20.38,16.99) v3(20.45,64.38) v3(20.45,50.52) v3(20.45,49.56) v3(20.45,33.25) v3(20.45,32.28) v3(20.45,18.43) v3(20.59,65.59) v3(20.59,17.21) v3(20.66,64.16) v3(20.66,18.64) v3(20.81,65.38) v3(20.75,50.52) v3(20.75,49.56) v3(20.75,33.25) v3(20.75,32.28) v3(20.81,17.43) v3(20.88,63.94) v3(20.88,18.86) v3(21.02,65.16) v3(21.02,17.64) v3(21.09,63.73) v3(21.06,50.52) v3(21.06,49.56) v3(21.06,33.25) v3(21.06,32.28) v3(21.09,19.08) v3(21.24,64.95) v3(21.24,17.86) v3(21.31,63.51) v3(21.31,19.29) v3(21.36,50.52) v3(21.36,49.56) v3(21.36,33.25) v3(21.36,32.28) v3(21.46,64.73) v3(21.52,63.3) v3(21.52,19.51) v3(21.46,18.07) v3(21.67,64.52) v3(21.74,63.08) v3(21.67,50.52) v3(21.67,49.56) v3(21.67,33.25) v3(21.67,32.28) v3(21.74,19.72) v3(21.67,18.29) v3(21.89,64.3) v3(21.89,18.5) v3(21.96,62.87) v3(21.97,50.52) v3(21.97,49.56) v3(21.97,33.25) v3(21.97,32.28) v3(21.96,19.94) v3(22.1,64.09) v3(22.1,18.72) v3(22.17,62.65) v3(22.17,20.15) v3(22.32,63.87) v3(22.28,50.52) v3(22.28,49.56) v3(22.28,33.25) v3(22.28,32.28) v3(22.32,18.93) v3(22.39,62.44) v3(22.39,20.37) v3(22.53,63.65) v3(22.53,19.15) v3(22.6,62.22) v3(22.58,50.52) v3(22.58,49.56) v3(22.58,33.25) v3(22.58,32.28) v3(22.6,20.58) v3(22.75,63.44) v3(22.82,62) v3(22.82,20.8) v3(22.75,19.37) v3(22.89,50.52) v3(22.89,49.56) v3(22.89,33.25) v3(22.89,32.28) v3(22.96,63.22) v3(23.03,61.79) v3(23.03,21.01) v3(22.96,19.58) v3(23.18,63.01) v3(23.19,50.52) v3(23.19,49.56) v3(23.19,33.25) v3(23.19,32.28) v3(23.18,19.8) v3(23.25,61.57) v3(23.25,21.23) v3(23.39,62.79) v3(23.39,20.01) v3(23.46,61.36) v3(23.5,50.52) v3(23.5,49.56) v3(23.5,33.25) v3(23.5,32.28) v3(23.46,21.45) v3(23.61,62.58) v3(23.61,20.23) v3(23.68,61.14) v3(23.68,21.66) v3(23.83,62.36) v3(23.8,50.52) v3(23.8,49.56) v3(23.8,33.25) v3(23.8,32.28) v3(23.83,20.44) v3(23.9,60.93) v3(23.9,21.88) v3(24.04,62.15) v3(24.04,20.66) v3(24.11,60.71) v3(24.11,50.52) v3(24.11,49.56) v3(24.11,33.25) v3(24.11,32.28) v3(24.11,22.09) v3(24.26,61.93) v3(24.33,60.5) v3(24.33,22.31) v3(24.26,20.87) v3(24.41,50.52) v3(24.41,49.56) v3(24.41,33.25) v3(24.41,32.28) v3(24.47,61.71) v3(24.54,60.28) v3(24.54,22.52) v3(24.47,21.09) v3(24.69,61.5) v3(24.72,50.52) v3(24.72,49.56) v3(24.72,33.25) v3(24.72,32.28) v3(24.69,21.31) v3(24.76,60.06) v3(24.76,22.74) v3(24.9,61.28) v3(24.9,21.52) v3(24.97,59.85) v3(25.02,50.52) v3(25.02,49.56) v3(25.02,33.25) v3(25.02,32.28) v3(24.97,22.95) v3(25.12,61.07) v3(25.12,21.74) v3(25.19,59.63) v3(25.19,23.17) v3(25.33,60.85) v3(25.33,50.52) v3(25.33,49.56) v3(25.33,33.25) v3(25.33,32.28) v3(25.33,21.95) v3(25.4,59.42) v3(25.4,23.39) v3(25.55,60.64) v3(25.62,59.2) v3(25.63,50.52) v3(25.63,49.56) v3(25.63,33.25) v3(25.63,32.28) v3(25.62,23.6) v3(25.55,22.17) v3(25.77,60.42) v3(25.83,58.99) v3(25.83,23.82) v3(25.77,22.38) v3(25.93,50.52) v3(25.93,49.55) v3(25.93,33.25) v3(25.93,32.29) v3(25.98,60.21) v3(25.98,22.6) v3(26.05,58.77) v3(26.05,24.03) v3(26.2,59.99) v3(26.24,50.5) v3(26.24,49.53) v3(26.24,33.27) v3(26.24,32.3) v3(26.2,22.81) v3(26.27,58.56) v3(26.27,24.25) v3(26.41,59.77) v3(26.41,23.03) v3(26.48,58.34) v3(26.54,50.47) v3(26.54,49.5) v3(26.54,33.3) v3(26.54,32.33) v3(26.48,24.46) v3(26.63,59.56) v3(26.63,23.24) v3(26.7,58.13) v3(26.7,24.68) v3(26.84,59.34) v3(26.84,50.43) v3(26.84,49.45) v3(26.84,33.35) v3(26.84,32.37) v3(26.84,23.46) v3(26.91,57.91) v3(26.91,24.89) v3(27.06,59.13) v3(27.13,57.69) v3(27.14,50.37) v3(27.14,49.39) v3(27.14,33.42) v3(27.14,32.43) v3(27.13,25.11) v3(27.06,23.68) v3(27.27,58.91) v3(27.34,57.48) v3(27.34,25.33) v3(27.27,23.89) v3(27.44,50.3) v3(27.43,49.3) v3(27.43,33.5) v3(27.44,32.5) v3(27.49,58.7) v3(27.49,24.11) v3(27.56,57.26) v3(27.56,25.54) v3(27.71,58.48) v3(27.73,50.22) v3(27.72,49.21) v3(27.72,33.6) v3(27.73,32.58) v3(27.71,24.32) v3(27.77,57.05) v3(27.77,25.76) v3(27.92,58.27) v3(27.92,24.54) v3(27.99,56.83) v3(28.02,50.13) v3(28.01,49.1) v3(28.01,33.71) v3(28.02,32.68) v3(27.99,25.97) v3(28.14,58.05) v3(28.14,24.75) v3(28.21,56.62) v3(28.21,26.19) v3(28.31,50.02) v3(28.29,48.97) v3(28.29,33.83) v3(28.31,32.79) v3(28.35,57.84) v3(28.42,56.4) v3(28.42,26.4) v3(28.35,24.97) v3(28.57,57.62) v3(28.64,56.19) v3(28.59,49.9) v3(28.56,48.83) v3(28.56,33.97) v3(28.59,32.91) v3(28.64,26.62) v3(28.57,25.18) v3(28.78,57.4) v3(28.82,48.68) v3(28.82,34.12) v3(28.78,25.4) v3(28.85,55.97) v3(28.86,49.76) v3(28.86,33.04) v3(28.85,26.83) v3(29,57.19) v3(29,25.62) v3(29.07,55.75) v3(29.13,49.62) v3(29.08,48.51) v3(29.08,34.29) v3(29.13,33.19) v3(29.07,27.05) v3(29.21,56.97) v3(29.21,25.83) v3(29.28,55.54) v3(29.32,48.33) v3(29.32,34.47) v3(29.28,27.27) v3(29.43,56.76) v3(29.39,49.46) v3(29.39,33.34) v3(29.43,26.05) v3(29.5,55.32) v3(29.5,27.48) v3(29.65,56.54) v3(29.65,49.29) v3(29.56,48.14) v3(29.56,34.66) v3(29.65,33.51) v3(29.65,26.26) v3(29.71,55.11) v3(29.71,27.7) v3(29.78,47.94) v3(29.78,34.87) v3(29.86,56.33) v3(29.93,54.89) v3(29.89,49.11) v3(29.89,33.69) v3(29.93,27.91) v3(29.86,26.48) v3(30,47.72) v3(30,35.08) v3(30.08,56.11) v3(30.15,54.68) v3(30.13,48.92) v3(30.13,33.88) v3(30.15,28.13) v3(30.08,26.69) v3(30.22,47.51) v3(30.22,35.3) v3(30.29,55.9) v3(30.29,26.91) v3(30.36,54.46) v3(30.36,48.72) v3(30.43,47.29) v3(30.43,35.51) v3(30.36,34.08) v3(30.36,28.34) v3(30.51,55.68) v3(30.51,27.12) v3(30.58,54.25) v3(30.58,48.51) v3(30.58,34.29) v3(30.58,28.56) v3(30.72,55.46) v3(30.65,47.08) v3(30.65,35.73) v3(30.72,27.34) v3(30.79,54.03) v3(30.79,48.29) v3(30.79,34.51) v3(30.79,28.77) v3(30.94,55.25) v3(30.86,46.86) v3(30.86,35.94) v3(30.94,27.56) v3(31.01,53.81) v3(31.01,48.08) v3(31.01,34.73) v3(31.01,28.99) v3(31.08,46.64) v3(31.08,36.16) v3(31.15,55.03) v3(31.22,53.6) v3(31.22,47.86) v3(31.22,34.94) v3(31.22,29.2) v3(31.15,27.77) v3(31.29,46.43) v3(31.29,36.37) v3(31.37,54.82) v3(31.44,53.38) v3(31.44,47.65) v3(31.44,35.16) v3(31.44,29.42) v3(31.37,27.99) v3(31.51,46.21) v3(31.51,36.59) v3(31.58,54.6) v3(31.58,28.2) v3(31.65,53.17) v3(31.66,47.43) v3(31.72,46) v3(31.72,36.81) v3(31.66,35.37) v3(31.65,29.64) v3(31.8,54.39) v3(31.8,28.42) v3(31.87,52.95) v3(31.87,47.22) v3(31.94,45.78) v3(31.94,37.02) v3(31.87,35.59) v3(31.87,29.85) v3(32.02,54.17) v3(32.02,28.63) v3(32.09,52.74) v3(32.09,47) v3(32.09,35.8) v3(32.09,30.07) v3(32.23,53.96) v3(32.16,45.57) v3(32.16,37.24) v3(32.23,28.85) v3(32.3,52.52) v3(32.3,46.79) v3(32.3,36.02) v3(32.3,30.28) v3(32.37,45.35) v3(32.37,37.45) v3(32.45,53.74) v3(32.52,52.31) v3(32.52,46.57) v3(32.52,36.23) v3(32.52,30.5) v3(32.45,29.06) v3(32.59,45.14) v3(32.59,37.67) v3(32.66,53.52) v3(32.73,52.09) v3(32.73,46.35) v3(32.73,36.45) v3(32.73,30.71) v3(32.66,29.28) v3(32.8,44.92) v3(32.8,37.88) v3(32.88,53.31) v3(32.88,29.49) v3(32.95,51.87) v3(32.95,46.14) v3(33.02,44.71) v3(33.02,38.1) v3(32.95,36.66) v3(32.95,30.93) v3(33.09,53.09) v3(33.09,29.71) v3(33.16,51.66) v3(33.16,45.92) v3(33.23,44.49) v3(33.23,38.31) v3(33.16,36.88) v3(33.16,31.14) v3(33.31,52.88) v3(33.31,29.93) v3(33.38,51.44) v3(33.38,45.71) v3(33.38,37.1) v3(33.38,31.36) v3(33.52,52.66) v3(33.45,44.27) v3(33.45,38.53) v3(33.52,30.14) v3(33.59,51.23) v3(33.6,45.49) v3(33.6,37.31) v3(33.59,31.58) v3(33.74,52.45) v3(33.67,44.06) v3(33.67,38.74) v3(33.74,30.36) v3(33.81,51.01) v3(33.81,45.28) v3(33.81,37.53) v3(33.81,31.79) v3(33.89,43.85) v3(33.89,38.95) v3(33.96,52.23) v3(34.02,50.8) v3(34.03,45.06) v3(34.03,37.74) v3(34.02,32.01) v3(33.96,30.57) v3(34.12,43.65) v3(34.12,39.15) v3(34.17,52.02) v3(34.24,50.58) v3(34.24,44.85) v3(34.24,37.96) v3(34.24,32.22) v3(34.17,30.79) v3(34.39,51.8) v3(34.35,43.46) v3(34.35,39.35) v3(34.39,31) v3(34.46,50.37) v3(34.46,44.63) v3(34.46,38.17) v3(34.46,32.44) v3(34.6,51.58) v3(34.59,43.27) v3(34.59,39.53) v3(34.6,31.22) v3(34.67,50.15) v3(34.69,44.43) v3(34.69,38.37) v3(34.67,32.65) v3(34.82,51.37) v3(34.84,43.09) v3(34.84,39.71) v3(34.82,31.43) v3(34.89,49.94) v3(34.92,44.24) v3(34.92,38.57) v3(34.89,32.87) v3(35.03,51.15) v3(35.03,31.65) v3(35.1,49.72) v3(35.1,42.92) v3(35.1,39.88) v3(35.1,33.08) v3(35.16,44.05) v3(35.16,38.75) v3(35.25,50.94) v3(35.32,49.5) v3(35.32,33.3) v3(35.25,31.87) v3(35.41,43.87) v3(35.35,42.76) v3(35.35,40.04) v3(35.41,38.93) v3(35.46,50.72) v3(35.53,49.29) v3(35.53,33.52) v3(35.46,32.08) v3(35.62,42.61) v3(35.62,40.19) v3(35.68,50.51) v3(35.67,43.7) v3(35.67,39.1) v3(35.68,32.3) v3(35.75,49.07) v3(35.75,33.73) v3(35.9,50.29) v3(35.93,43.55) v3(35.89,42.47) v3(35.89,40.34) v3(35.93,39.26) v3(35.9,32.51) v3(35.96,48.86) v3(35.96,33.95) v3(36.11,50.08) v3(36.11,32.73) v3(36.18,48.64) v3(36.19,43.4) v3(36.16,42.33) v3(36.16,40.47) v3(36.19,39.41) v3(36.18,34.16) v3(36.33,49.86) v3(36.33,32.94) v3(36.4,48.43) v3(36.44,42.2) v3(36.44,40.6) v3(36.4,34.38) v3(36.54,49.65) v3(36.46,43.26) v3(36.46,39.55) v3(36.54,33.16) v3(36.61,48.21) v3(36.61,34.59) v3(36.74,43.13) v3(36.72,42.09) v3(36.72,40.72) v3(36.74,39.68) v3(36.76,49.43) v3(36.83,48) v3(36.83,34.81) v3(36.76,33.37) v3(36.97,49.21) v3(37.04,47.78) v3(37.02,43.01) v3(37,41.98) v3(37,40.83) v3(37.02,39.8) v3(37.04,35.02) v3(36.97,33.59) v3(37.19,49) v3(37.19,33.81) v3(37.26,47.56) v3(37.3,42.9) v3(37.29,41.88) v3(37.29,40.92) v3(37.3,39.91) v3(37.26,35.24) v3(37.4,48.78) v3(37.4,34.02) v3(37.47,47.35) v3(37.47,35.46) v3(37.62,48.57) v3(37.59,42.8) v3(37.58,41.79) v3(37.58,41.01) v3(37.59,40.01) v3(37.62,34.24) v3(37.69,47.13) v3(37.69,35.67) v3(37.84,48.35) v3(37.84,34.45) v3(37.9,46.92) v3(37.88,42.71) v3(37.88,41.71) v3(37.88,41.09) v3(37.88,40.1) v3(37.9,35.89) v3(37.94,25.18) v3(37.89,24.88) v3(37.86,24.58) v3(37.85,24.28) v3(37.85,23.97) v3(37.85,23.67) v3(37.85,23.36) v3(37.85,23.06) v3(37.85,22.75) v3(37.85,22.45) v3(37.85,22.14) v3(37.85,21.84) v3(37.85,21.53) v3(37.85,21.23) v3(37.85,20.92) v3(37.85,20.62) v3(37.85,20.31) v3(37.85,20.01) v3(37.85,19.7) v3(37.85,19.4) v3(37.85,19.09) v3(37.85,18.79) v3(37.85,18.49) v3(37.85,18.18) v3(37.85,17.88) v3(37.85,17.57) v3(37.85,17.27) v3(37.85,16.96) v3(37.85,16.66) v3(37.85,16.35) v3(37.85,16.05) v3(37.85,15.74) v3(37.85,15.44) v3(37.85,15.13) v3(37.85,14.83) v3(37.85,14.52) v3(37.85,14.22) v3(37.85,13.91) v3(37.85,13.61) v3(37.85,13.3) v3(37.85,13) v3(37.85,12.69) v3(37.85,12.39) v3(37.85,12.08) v3(37.85,11.78) v3(37.85,11.47) v3(37.85,11.17) v3(37.85,10.87) v3(37.85,10.56) v3(37.85,10.26) v3(37.85,9.95) v3(37.85,9.65) v3(37.85,9.34) v3(37.85,9.04) v3(37.85,8.73) v3(37.85,8.43) v3(37.85,8.12) v3(37.85,7.82) v3(38.03,25.48) v3(38.05,48.14) v3(38.12,46.7) v3(38.12,36.1) v3(38.05,34.67) v3(38.13,25.76) v3(38.18,42.63) v3(38.17,41.64) v3(38.17,41.16) v3(38.18,40.17) v3(38.27,47.92) v3(38.34,46.49) v3(38.34,36.32) v3(38.27,34.88) v3(38.27,26.04) v3(38.42,26.3) v3(38.48,47.71) v3(38.47,42.56) v3(38.47,41.58) v3(38.47,41.23) v3(38.47,40.24) v3(38.48,35.1) v3(38.55,46.27) v3(38.55,36.53) v3(38.6,26.55) v3(38.7,47.49) v3(38.7,35.31) v3(38.77,46.06) v3(38.77,42.51) v3(38.77,41.53) v3(38.77,41.28) v3(38.77,40.3) v3(38.77,36.75) v3(38.8,26.78) v3(38.83,24.58) v3(38.82,24.28) v3(38.82,23.97) v3(38.82,23.67) v3(38.82,23.36) v3(38.82,23.06) v3(38.82,22.75) v3(38.82,22.45) v3(38.82,22.14) v3(38.82,21.84) v3(38.82,21.53) v3(38.82,21.23) v3(38.82,20.92) v3(38.82,20.62) v3(38.82,20.31) v3(38.82,20.01) v3(38.82,19.7) v3(38.82,19.4) v3(38.82,19.1) v3(38.82,18.79) v3(38.82,18.49) v3(38.82,18.18) v3(38.82,17.88) v3(38.82,17.57) v3(38.82,17.27) v3(38.82,16.96) v3(38.82,16.66) v3(38.82,16.35) v3(38.82,16.05) v3(38.82,15.74) v3(38.82,15.44) v3(38.82,15.13) v3(38.82,14.83) v3(38.82,14.52) v3(38.82,14.22) v3(38.82,13.91) v3(38.82,13.61) v3(38.82,13.3) v3(38.82,13) v3(38.82,12.69) v3(38.82,12.39) v3(38.82,12.08) v3(38.82,11.78) v3(38.82,11.48) v3(38.82,11.17) v3(38.82,10.87) v3(38.82,10.56) v3(38.82,10.26) v3(38.82,9.95) v3(38.82,9.65) v3(38.82,9.34) v3(38.82,9.04) v3(38.82,8.73) v3(38.82,8.43) v3(38.82,8.12) v3(38.82,7.82) v3(38.91,47.27) v3(38.91,35.53) v3(38.94,25.18) v3(38.87,24.88) v3(38.98,45.84) v3(38.98,36.96) v3(39.02,26.99) v3(39.13,47.06) v3(39.08,42.46) v3(39.07,41.49) v3(39.08,40.34) v3(39.13,35.75) v3(39.06,25.46) v3(39.2,45.62) v3(39.2,37.18) v3(39.23,27.21) v3(39.2,25.73) v3(39.34,46.84) v3(39.34,35.96) v3(39.41,45.41) v3(39.38,42.42) v3(39.38,41.46) v3(39.38,40.38) v3(39.41,37.39) v3(39.38,25.98) v3(39.45,27.42) v3(39.56,46.63) v3(39.63,45.19) v3(39.63,37.61) v3(39.56,36.18) v3(39.59,26.2) v3(39.68,42.4) v3(39.68,41.43) v3(39.68,40.4) v3(39.66,27.64) v3(39.77,46.41) v3(39.84,44.98) v3(39.84,37.83) v3(39.77,36.39) v3(39.8,26.41) v3(39.88,27.85) v3(39.99,46.2) v3(39.99,41.42) v3(39.99,40.42) v3(39.99,36.61) v3(40.02,26.63) v3(40.06,44.76) v3(40.06,38.04) v3(40.09,28.07) v3(40.21,45.98) v3(40.21,36.82) v3(40.24,26.85) v3(40.28,44.55) v3(40.29,41.42) v3(40.29,40.42) v3(40.28,38.26) v3(40.31,28.28) v3(40.42,45.77) v3(40.42,37.04) v3(40.49,44.33) v3(40.49,38.47) v3(40.53,28.5) v3(40.45,27.06) v3(40.64,45.55) v3(40.6,41.42) v3(40.6,40.42) v3(40.64,37.25) v3(40.71,44.12) v3(40.71,38.68) v3(40.74,28.72) v3(40.67,27.28) v3(40.85,45.33) v3(40.94,43.92) v3(40.9,40.42) v3(40.94,38.88) v3(40.85,37.47) v3(40.88,27.49) v3(40.96,28.93) v3(41.07,45.12) v3(41.07,37.68) v3(41.1,27.71) v3(41.19,43.74) v3(41.21,42.38) v3(41.21,40.42) v3(41.19,39.07) v3(41.17,29.15) v3(41.29,44.91) v3(41.29,37.9) v3(41.31,27.92) v3(41.43,43.56) v3(41.43,39.24) v3(41.39,29.36) v3(41.52,44.71) v3(41.51,42.38) v3(41.51,40.42) v3(41.52,38.1) v3(41.53,28.14) v3(41.6,29.58) v3(41.69,43.4) v3(41.69,39.41) v3(41.74,28.35) v3(41.75,44.52) v3(41.82,42.38) v3(41.82,40.42) v3(41.75,38.29) v3(41.82,29.79) v3(42,44.34) v3(41.95,43.24) v3(41.95,39.56) v3(42,38.46) v3(42.03,30.01) v3(41.96,28.57) v3(42.12,42.38) v3(42.12,41.42) v3(42.22,43.1) v3(42.22,39.7) v3(42.18,28.79) v3(42.26,44.18) v3(42.26,38.63) v3(42.25,30.22) v3(42.42,42.38) v3(42.42,41.42) v3(42.39,29) v3(42.53,44.03) v3(42.5,42.98) v3(42.5,39.83) v3(42.53,38.77) v3(42.47,30.44) v3(42.61,29.22) v3(42.73,42.38) v3(42.73,41.42) v3(42.68,30.66) v3(42.8,43.9) v3(42.78,42.86) v3(42.8,38.91) v3(42.82,29.43) v3(42.9,30.87) v3(43.03,42.38) v3(43.03,41.42) v3(43.04,29.65) v3(43.08,43.78) v3(43.07,42.76) v3(43.08,39.03) v3(43.11,31.09) v3(43.34,42.38) v3(43.34,41.42) v3(43.33,31.3) v3(43.25,29.86) v3(43.37,43.67) v3(43.36,42.67) v3(43.37,39.13) v3(43.54,31.52) v3(43.47,30.08) v3(43.64,41.42) v3(43.66,43.59) v3(43.66,42.59) v3(43.66,39.22) v3(43.68,30.29) v3(43.76,31.73) v3(43.9,30.51) v3(43.96,43.51) v3(43.96,42.53) v3(43.95,41.42) v3(43.96,39.29) v3(43.97,31.95) v3(44.12,30.72) v3(44.19,32.16) v3(44.26,43.46) v3(44.26,42.48) v3(44.25,41.42) v3(44.26,39.35) v3(44.33,30.94) v3(44.41,32.38) v3(44.55,31.16) v3(44.56,43.42) v3(44.56,42.45) v3(44.56,41.42) v3(44.56,39.39) v3(44.62,32.6) v3(44.84,32.81) v3(44.76,31.37) v3(44.86,43.39) v3(44.86,42.43) v3(44.86,41.42) v3(44.86,39.41) v3(44.98,31.59) v3(45.05,33.03) v3(45.17,43.38) v3(45.17,42.42) v3(45.17,41.42) v3(45.17,39.42) v3(45.19,31.8) v3(45.27,33.24) v3(45.41,32.02) v3(45.47,43.38) v3(45.47,42.42) v3(45.47,41.42) v3(45.47,39.42) v3(45.48,33.46) v3(45.62,32.23) v3(45.7,33.67) v3(45.78,43.38) v3(45.78,42.42) v3(45.78,41.42) v3(45.78,39.42) v3(45.84,32.45) v3(45.91,33.89) v3(46.08,43.38) v3(46.08,42.42) v3(46.08,41.42) v3(46.08,39.42) v3(46.13,34.1) v3(46.06,32.66) v3(46.34,34.32) v3(46.27,32.88) v3(46.39,43.38) v3(46.39,42.42) v3(46.39,41.42) v3(46.39,39.42) v3(46.49,33.1) v3(46.56,34.53) v3(46.69,43.38) v3(46.69,42.42) v3(46.69,41.42) v3(46.69,39.42) v3(46.7,33.31) v3(46.78,34.75) v3(46.92,33.53) v3(47,43.38) v3(47,42.42) v3(47,41.42) v3(47,40.41) v3(47,39.42) v3(46.99,34.97) v3(47.13,33.74) v3(47.19,35.2) v3(47.3,43.39) v3(47.3,42.41) v3(47.3,41.41) v3(47.3,40.41) v3(47.3,39.41) v3(47.34,35.46) v3(47.45,35.75) v3(47.35,33.96) v3(47.49,43.15) v3(47.49,42.85) v3(47.48,42.6) v3(47.51,42.21) v3(47.49,41.95) v3(47.49,41.65) v3(47.49,41.19) v3(47.49,40.89) v3(47.49,40.61) v3(47.49,40.2) v3(47.5,39.9) v3(47.51,39.63) v3(47.51,39.4) v3(47.51,39.1) v3(47.51,38.79) v3(47.51,38.49) v3(47.51,38.18) v3(47.51,37.88) v3(47.51,37.57) v3(47.51,37.27) v3(47.51,36.96) v3(47.51,36.66) v3(47.51,36.35) v3(47.5,36.05) v3(47.56,34.17) v3(47.8,39.91) v3(47.78,34.39) v3(47.97,34.63) v3(48.11,39.9) v3(48.13,34.89) v3(48.26,35.16) v3(48.36,39.91) v3(48.43,35.75) v3(48.36,35.45) v3(48.5,40.4) v3(48.5,40.14) v3(48.49,39.68) v3(48.48,39.4) v3(48.48,39.1) v3(48.48,38.79) v3(48.48,38.49) v3(48.48,38.18) v3(48.48,37.88) v3(48.48,37.57) v3(48.48,37.27) v3(48.48,36.96) v3(48.48,36.66) v3(48.48,36.35) v3(48.47,36.05) v3(48.63,35.45) v3(48.69,39.91) v3(48.73,35.16) v3(48.87,34.89) v3(49,39.9) v3(49.03,34.63) v3(49.22,34.39) v3(49.26,39.9) v3(49.43,34.17) v3(49.5,43.24) v3(49.5,42.93) v3(49.51,42.67) v3(49.5,42.4) v3(49.5,42.16) v3(49.48,41.9) v3(49.49,41.59) v3(49.5,41.16) v3(49.5,40.86) v3(49.5,40.57) v3(49.49,40.21) v3(49.5,39.91) v3(49.49,39.61) v3(49.48,39.4) v3(49.48,39.1) v3(49.48,38.79) v3(49.48,38.49) v3(49.48,38.18) v3(49.48,37.88) v3(49.48,37.57) v3(49.48,37.27) v3(49.48,36.96) v3(49.48,36.66) v3(49.48,36.35) v3(49.49,36.05) v3(49.55,35.75) v3(49.65,33.96) v3(49.74,43.4) v3(49.74,42.4) v3(49.69,41.39) v3(49.73,40.4) v3(49.7,39.39) v3(49.66,35.46) v3(49.81,35.2) v3(49.86,33.74) v3(50,43.38) v3(50,42.38) v3(50,41.42) v3(50,40.38) v3(50,39.42) v3(50,34.97) v3(50.08,33.53) v3(50.22,34.75) v3(50.3,43.38) v3(50.3,42.38) v3(50.3,41.42) v3(50.3,40.38) v3(50.3,39.42) v3(50.29,33.31) v3(50.43,34.53) v3(50.51,33.1) v3(50.61,43.38) v3(50.61,42.38) v3(50.61,41.42) v3(50.61,40.38) v3(50.61,39.42) v3(50.65,34.32) v3(50.72,32.88) v3(50.91,43.38) v3(50.91,42.38) v3(50.91,41.42) v3(50.91,40.38) v3(50.91,39.42) v3(50.86,34.1) v3(50.94,32.66) v3(51.08,33.89) v3(51.22,43.38) v3(51.22,42.38) v3(51.22,40.38) v3(51.22,39.42) v3(51.15,32.45) v3(51.3,33.67) v3(51.37,32.23) v3(51.52,43.38) v3(51.52,42.38) v3(51.52,40.38) v3(51.52,39.42) v3(51.51,33.46) v3(51.58,32.02) v3(51.73,33.24) v3(51.83,43.38) v3(51.83,42.38) v3(51.83,40.38) v3(51.83,39.42) v3(51.8,31.8) v3(51.94,33.03) v3(52.02,31.59) v3(52.13,43.39) v3(52.13,40.38) v3(52.13,39.41) v3(52.16,32.81) v3(52.23,31.37) v3(52.43,43.42) v3(52.43,40.36) v3(52.43,39.39) v3(52.37,32.6) v3(52.45,31.16) v3(52.59,32.38) v3(52.74,43.46) v3(52.74,40.32) v3(52.74,39.35) v3(52.66,30.94) v3(52.8,32.16) v3(52.88,30.72) v3(53.04,40.27) v3(53.04,39.29) v3(53.02,31.95) v3(53.09,30.51) v3(53.23,31.73) v3(53.34,40.21) v3(53.33,39.22) v3(53.31,30.29) v3(53.35,41.42) v3(53.45,31.52) v3(53.52,30.08) v3(53.63,42.67) v3(53.63,40.14) v3(53.62,39.13) v3(53.65,41.42) v3(53.65,40.42) v3(53.67,31.3) v3(53.74,29.86) v3(53.92,42.76) v3(53.92,40.05) v3(53.91,39.03) v3(53.88,31.09) v3(53.96,41.42) v3(53.96,40.42) v3(53.96,29.65) v3(54.1,30.87) v3(54.21,42.86) v3(54.21,39.94) v3(54.19,38.91) v3(54.17,29.43) v3(54.26,42.38) v3(54.26,41.42) v3(54.26,40.42) v3(54.31,30.66) v3(54.39,29.22) v3(54.47,44.04) v3(54.49,42.98) v3(54.49,39.83) v3(54.46,38.77) v3(54.53,30.44) v3(54.57,42.38) v3(54.57,41.42) v3(54.57,40.42) v3(54.6,29) v3(54.73,44.18) v3(54.73,38.63) v3(54.74,30.22) v3(54.77,43.1) v3(54.77,39.7) v3(54.82,28.79) v3(54.87,42.38) v3(54.87,41.42) v3(54.87,40.42) v3(54.99,44.34) v3(55.04,43.24) v3(55.04,39.56) v3(54.99,38.46) v3(54.96,30.01) v3(55.03,28.57) v3(55.24,44.52) v3(55.18,42.38) v3(55.18,41.42) v3(55.18,40.42) v3(55.24,38.29) v3(55.17,29.79) v3(55.3,43.4) v3(55.3,39.41) v3(55.25,28.35) v3(55.39,29.58) v3(55.48,44.71) v3(55.48,42.38) v3(55.48,41.42) v3(55.48,40.42) v3(55.48,38.1) v3(55.46,28.14) v3(55.56,43.56) v3(55.56,39.24) v3(55.61,29.36) v3(55.71,44.91) v3(55.71,37.9) v3(55.68,27.92) v3(55.81,43.74) v3(55.79,42.38) v3(55.79,41.42) v3(55.79,40.42) v3(55.81,39.07) v3(55.82,29.15) v3(55.93,45.12) v3(55.93,37.68) v3(55.9,27.71) v3(56.04,28.93) v3(56.14,45.33) v3(56.05,43.92) v3(56.09,42.38) v3(56.09,41.42) v3(56.09,40.42) v3(56.05,38.88) v3(56.14,37.47) v3(56.11,27.49) v3(56.28,44.12) v3(56.28,38.68) v3(56.25,28.72) v3(56.33,27.28) v3(56.36,45.55) v3(56.4,42.38) v3(56.4,41.42) v3(56.4,40.42) v3(56.36,37.25) v3(56.5,44.33) v3(56.5,38.47) v3(56.47,28.5) v3(56.54,27.06) v3(56.57,45.77) v3(56.57,37.04) v3(56.72,44.55) v3(56.7,42.38) v3(56.7,41.42) v3(56.7,40.42) v3(56.72,38.26) v3(56.68,28.28) v3(56.79,45.98) v3(56.79,36.82) v3(56.76,26.85) v3(56.93,44.76) v3(56.93,38.04) v3(56.9,28.07) v3(57,46.2) v3(57.01,42.39) v3(57.01,41.42) v3(57.01,40.42) v3(57,36.61) v3(56.97,26.63) v3(57.11,27.85) v3(57.22,46.41) v3(57.15,44.98) v3(57.15,37.83) v3(57.22,36.39) v3(57.19,26.41) v3(57.31,42.4) v3(57.31,41.43) v3(57.31,40.4) v3(57.33,27.64) v3(57.43,46.63) v3(57.36,45.19) v3(57.36,37.61) v3(57.43,36.18) v3(57.4,26.2) v3(57.55,27.42) v3(57.58,45.41) v3(57.62,42.42) v3(57.62,41.46) v3(57.62,40.38) v3(57.58,37.39) v3(57.61,25.98) v3(57.65,46.84) v3(57.65,35.96) v3(57.8,45.62) v3(57.8,37.18) v3(57.76,27.21) v3(57.79,25.73) v3(57.87,47.06) v3(57.92,42.46) v3(57.92,41.49) v3(57.92,41.32) v3(57.92,40.34) v3(57.87,35.75) v3(57.94,25.46) v3(58.01,45.84) v3(58.01,36.96) v3(57.98,26.99) v3(58.08,47.27) v3(58.08,35.53) v3(58.05,25.18) v3(58.13,24.88) v3(58.23,46.06) v3(58.22,42.51) v3(58.22,41.53) v3(58.22,41.28) v3(58.22,40.3) v3(58.23,36.75) v3(58.19,26.78) v3(58.17,24.58) v3(58.17,24.28) v3(58.17,23.97) v3(58.17,23.67) v3(58.17,23.36) v3(58.17,23.06) v3(58.17,22.75) v3(58.17,22.45) v3(58.17,22.14) v3(58.17,21.84) v3(58.17,21.53) v3(58.17,21.23) v3(58.17,20.92) v3(58.17,20.62) v3(58.17,20.31) v3(58.17,20.01) v3(58.17,19.7) v3(58.17,19.4) v3(58.17,19.1) v3(58.17,18.79) v3(58.17,18.49) v3(58.17,18.18) v3(58.17,17.88) v3(58.17,17.57) v3(58.17,17.27) v3(58.17,16.96) v3(58.17,16.66) v3(58.17,16.35) v3(58.17,16.05) v3(58.17,15.74) v3(58.17,15.44) v3(58.17,15.13) v3(58.17,14.83) v3(58.17,14.52) v3(58.17,14.22) v3(58.17,13.91) v3(58.17,13.61) v3(58.17,13.3) v3(58.17,13) v3(58.17,12.69) v3(58.17,12.39) v3(58.17,12.08) v3(58.17,11.78) v3(58.17,11.48) v3(58.17,11.17) v3(58.17,10.87) v3(58.17,10.56) v3(58.17,10.26) v3(58.17,9.95) v3(58.17,9.65) v3(58.17,9.34) v3(58.17,9.04) v3(58.17,8.73) v3(58.17,8.43) v3(58.17,8.12) v3(58.17,7.82) v3(58.3,47.49) v3(58.3,35.31) v3(58.44,46.27) v3(58.44,36.53) v3(58.39,26.55) v3(58.51,47.71) v3(58.52,42.56) v3(58.52,41.58) v3(58.52,41.23) v3(58.52,40.24) v3(58.51,35.1) v3(58.57,26.3) v3(58.73,47.92) v3(58.66,46.49) v3(58.66,36.32) v3(58.73,34.88) v3(58.73,26.04) v3(58.82,42.63) v3(58.82,41.64) v3(58.82,41.16) v3(58.82,40.17) v3(58.94,48.14) v3(58.87,46.7) v3(58.87,36.1) v3(58.94,34.67) v3(58.86,25.76) v3(58.97,25.48) v3(59.09,46.92) v3(59.11,42.71) v3(59.12,41.71) v3(59.12,41.09) v3(59.11,40.1) v3(59.09,35.89) v3(59.05,25.18) v3(59.11,24.88) v3(59.14,24.58) v3(59.14,24.28) v3(59.14,23.97) v3(59.14,23.67) v3(59.14,23.36) v3(59.14,23.06) v3(59.14,22.75) v3(59.14,22.45) v3(59.14,22.14) v3(59.14,21.84) v3(59.14,21.53) v3(59.14,21.23) v3(59.14,20.92) v3(59.14,20.62) v3(59.14,20.31) v3(59.14,20.01) v3(59.14,19.7) v3(59.14,19.4) v3(59.14,19.09) v3(59.14,18.79) v3(59.14,18.49) v3(59.14,18.18) v3(59.14,17.88) v3(59.14,17.57) v3(59.14,17.27) v3(59.14,16.96) v3(59.14,16.66) v3(59.14,16.35) v3(59.14,16.05) v3(59.14,15.74) v3(59.14,15.44) v3(59.14,15.13) v3(59.14,14.83) v3(59.14,14.52) v3(59.14,14.22) v3(59.14,13.91) v3(59.14,13.61) v3(59.14,13.3) v3(59.14,13) v3(59.14,12.69) v3(59.14,12.39) v3(59.14,12.08) v3(59.14,11.78) v3(59.14,11.47) v3(59.14,11.17) v3(59.14,10.87) v3(59.14,10.56) v3(59.14,10.26) v3(59.14,9.95) v3(59.14,9.65) v3(59.14,9.34) v3(59.14,9.04) v3(59.14,8.73) v3(59.14,8.43) v3(59.14,8.12) v3(59.14,7.82) v3(59.16,48.35) v3(59.16,34.45) v3(59.3,47.13) v3(59.3,35.67) v3(59.37,48.57) v3(59.4,42.8) v3(59.41,41.79) v3(59.41,41.01) v3(59.4,40.01) v3(59.37,34.24) v3(59.52,47.35) v3(59.52,35.46) v3(59.59,48.78) v3(59.59,34.02) v3(59.74,47.56) v3(59.69,42.9) v3(59.7,41.88) v3(59.7,40.92) v3(59.69,39.91) v3(59.74,35.24) v3(59.8,49) v3(59.8,33.81) v3(60.02,49.21) v3(59.95,47.78) v3(59.97,43.01) v3(59.99,41.98) v3(59.99,40.83) v3(59.97,39.8) v3(59.95,35.02) v3(60.02,33.59) v3(60.24,49.43) v3(60.17,48) v3(60.17,34.81) v3(60.24,33.37) v3(60.26,43.13) v3(60.28,42.09) v3(60.28,40.72) v3(60.26,39.68) v3(60.38,48.21) v3(60.38,34.59) v3(60.45,49.65) v3(60.53,43.26) v3(60.53,39.55) v3(60.45,33.16) v3(60.6,48.43) v3(60.56,42.2) v3(60.56,40.6) v3(60.6,34.38) v3(60.67,49.86) v3(60.67,32.94) v3(60.81,48.64) v3(60.8,43.4) v3(60.83,42.33) v3(60.83,40.47) v3(60.8,39.41) v3(60.81,34.16) v3(60.88,50.08) v3(60.88,32.73) v3(61.03,48.86) v3(61.03,33.95) v3(61.1,50.29) v3(61.07,43.55) v3(61.11,42.47) v3(61.11,40.34) v3(61.07,39.26) v3(61.1,32.51) v3(61.24,49.07) v3(61.24,33.73) v3(61.31,50.51) v3(61.33,43.7) v3(61.33,39.1) v3(61.31,32.3) v3(61.38,42.61) v3(61.38,40.19) v3(61.53,50.72) v3(61.46,49.29) v3(61.46,33.52) v3(61.53,32.08) v3(61.58,43.87) v3(61.64,42.76) v3(61.64,40.04) v3(61.58,38.93) v3(61.74,50.94) v3(61.68,49.5) v3(61.68,33.3) v3(61.74,31.87) v3(61.83,44.05) v3(61.83,38.75) v3(61.89,49.72) v3(61.9,42.92) v3(61.9,39.88) v3(61.89,33.08) v3(61.96,51.15) v3(61.96,31.65) v3(62.11,49.94) v3(62.07,44.24) v3(62.07,38.57) v3(62.11,32.87) v3(62.18,51.37) v3(62.15,43.09) v3(62.15,39.71) v3(62.18,31.43) v3(62.32,50.15) v3(62.3,44.43) v3(62.3,38.37) v3(62.32,32.65) v3(62.39,51.58) v3(62.4,43.27) v3(62.4,39.53) v3(62.39,31.22) v3(62.54,50.37) v3(62.53,44.63) v3(62.53,38.17) v3(62.54,32.44) v3(62.61,51.8) v3(62.64,43.46) v3(62.64,39.35) v3(62.61,31) v3(62.82,52.02) v3(62.75,50.58) v3(62.75,44.85) v3(62.75,37.96) v3(62.75,32.22) v3(62.82,30.79) v3(62.88,43.65) v3(62.88,39.15) v3(63.04,52.23) v3(62.97,50.8) v3(62.97,45.06) v3(62.97,37.74) v3(62.97,32.01) v3(63.04,30.57) v3(63.11,43.85) v3(63.11,38.95) v3(63.18,51.01) v3(63.18,45.28) v3(63.18,37.53) v3(63.18,31.79) v3(63.25,52.45) v3(63.33,44.06) v3(63.33,38.74) v3(63.25,30.36) v3(63.4,51.23) v3(63.4,45.49) v3(63.4,37.31) v3(63.4,31.58) v3(63.47,52.66) v3(63.54,44.27) v3(63.54,38.53) v3(63.47,30.14) v3(63.62,51.44) v3(63.61,45.71) v3(63.61,37.1) v3(63.62,31.36) v3(63.68,52.88) v3(63.68,29.93) v3(63.83,51.66) v3(63.83,45.92) v3(63.76,44.49) v3(63.76,38.31) v3(63.83,36.88) v3(63.83,31.14) v3(63.9,53.09) v3(63.9,29.71) v3(64.05,51.87) v3(64.04,46.14) v3(63.98,44.71) v3(63.98,38.1) v3(64.04,36.66) v3(64.05,30.93) v3(64.12,53.31) v3(64.12,29.49) v3(64.19,44.92) v3(64.19,37.88) v3(64.33,53.52) v3(64.26,52.09) v3(64.26,46.35) v3(64.26,36.45) v3(64.26,30.71) v3(64.33,29.28) v3(64.41,45.14) v3(64.41,37.67) v3(64.55,53.74) v3(64.48,52.31) v3(64.48,46.57) v3(64.48,36.23) v3(64.48,30.5) v3(64.55,29.06) v3(64.62,45.35) v3(64.62,37.45) v3(64.69,52.52) v3(64.69,46.79) v3(64.69,36.02) v3(64.69,30.28) v3(64.76,53.96) v3(64.84,45.57) v3(64.84,37.24) v3(64.76,28.85) v3(64.91,52.74) v3(64.91,47) v3(64.91,35.8) v3(64.91,30.07) v3(64.98,54.17) v3(64.98,28.63) v3(65.12,52.95) v3(65.12,47.22) v3(65.05,45.78) v3(65.05,37.02) v3(65.12,35.59) v3(65.12,29.85) v3(65.19,54.39) v3(65.19,28.42) v3(65.34,53.17) v3(65.34,47.43) v3(65.27,46) v3(65.27,36.81) v3(65.34,35.37) v3(65.34,29.64) v3(65.41,54.6) v3(65.41,28.2) v3(65.48,46.21) v3(65.48,36.59) v3(65.62,54.82) v3(65.55,53.38) v3(65.55,47.65) v3(65.55,35.16) v3(65.55,29.42) v3(65.62,27.99) v3(65.7,46.43) v3(65.7,36.37) v3(65.84,55.03) v3(65.77,53.6) v3(65.77,47.86) v3(65.77,34.94) v3(65.77,29.2) v3(65.84,27.77) v3(65.92,46.64) v3(65.92,36.16) v3(65.99,53.81) v3(65.98,48.08) v3(65.98,34.73) v3(65.99,28.99) v3(66.06,55.25) v3(66.13,46.86) v3(66.13,35.94) v3(66.06,27.56) v3(66.2,54.03) v3(66.2,48.29) v3(66.2,34.51) v3(66.2,28.77) v3(66.27,55.46) v3(66.35,47.08) v3(66.35,35.73) v3(66.27,27.34) v3(66.42,54.25) v3(66.42,48.51) v3(66.42,34.29) v3(66.42,28.56) v3(66.49,55.68) v3(66.49,27.12) v3(66.63,54.46) v3(66.64,48.72) v3(66.56,47.29) v3(66.56,35.51) v3(66.64,34.08) v3(66.63,28.34) v3(66.7,55.9) v3(66.7,26.91) v3(66.78,47.51) v3(66.78,35.3) v3(66.92,56.11) v3(66.85,54.68) v3(66.86,48.92) v3(66.86,33.88) v3(66.85,28.13) v3(66.92,26.69) v3(66.99,47.72) v3(66.99,35.08) v3(67.13,56.33) v3(67.06,54.89) v3(67.1,49.11) v3(67.1,33.69) v3(67.06,27.91) v3(67.13,26.48) v3(67.21,47.94) v3(67.21,34.87) v3(67.28,55.11) v3(67.28,27.7) v3(67.35,56.54) v3(67.35,49.29) v3(67.44,48.14) v3(67.44,34.66) v3(67.35,33.51) v3(67.35,26.26) v3(67.49,55.32) v3(67.49,27.48) v3(67.56,56.76) v3(67.6,49.46) v3(67.6,33.34) v3(67.56,26.05) v3(67.71,55.54) v3(67.67,48.33) v3(67.67,34.47) v3(67.71,27.27) v3(67.78,56.97) v3(67.78,25.83) v3(67.93,55.75) v3(67.86,49.62) v3(67.92,48.51) v3(67.92,34.29) v3(67.86,33.19) v3(67.93,27.05) v3(67.99,57.19) v3(67.99,25.62) v3(68.14,55.97) v3(68.13,49.76) v3(68.13,33.04) v3(68.14,26.83) v3(68.21,57.4) v3(68.17,48.68) v3(68.17,34.12) v3(68.21,25.4) v3(68.43,57.62) v3(68.36,56.19) v3(68.41,49.9) v3(68.44,48.83) v3(68.44,33.97) v3(68.41,32.91) v3(68.36,26.62) v3(68.43,25.18) v3(68.64,57.84) v3(68.57,56.4) v3(68.57,26.4) v3(68.64,24.97) v3(68.69,50.02) v3(68.71,48.97) v3(68.71,33.83) v3(68.69,32.79) v3(68.79,56.62) v3(68.79,26.19) v3(68.86,58.05) v3(68.86,24.75) v3(69,56.83) v3(68.97,50.13) v3(68.99,49.1) v3(68.99,33.71) v3(68.97,32.68) v3(69,25.97) v3(69.07,58.27) v3(69.07,24.54) v3(69.22,57.05) v3(69.22,25.76) v3(69.29,58.48) v3(69.26,50.22) v3(69.27,49.21) v3(69.27,33.6) v3(69.26,32.58) v3(69.29,24.32) v3(69.43,57.26) v3(69.43,25.54) v3(69.5,58.7) v3(69.5,24.11) v3(69.55,50.3) v3(69.56,49.3) v3(69.56,33.5) v3(69.55,32.5) v3(69.72,58.91) v3(69.65,57.48) v3(69.65,25.33) v3(69.72,23.89) v3(69.93,59.13) v3(69.87,57.69) v3(69.85,50.37) v3(69.85,49.39) v3(69.85,33.42) v3(69.85,32.43) v3(69.87,25.11) v3(69.93,23.68) v3(70.08,57.91) v3(70.08,24.89) v3(70.15,59.34) v3(70.15,50.43) v3(70.15,49.45) v3(70.15,33.35) v3(70.15,32.37) v3(70.15,23.46) v3(70.3,58.13) v3(70.3,24.68) v3(70.37,59.56) v3(70.37,23.24) v3(70.51,58.34) v3(70.45,50.47) v3(70.45,49.5) v3(70.45,33.3) v3(70.45,32.33) v3(70.51,24.46) v3(70.58,59.77) v3(70.58,23.03) v3(70.73,58.56) v3(70.73,24.25) v3(70.8,59.99) v3(70.75,50.5) v3(70.75,49.53) v3(70.75,33.27) v3(70.75,32.3) v3(70.8,22.81) v3(70.94,58.77) v3(70.94,24.03) v3(71.01,60.21) v3(71.01,22.6) v3(71.06,50.52) v3(71.06,49.55) v3(71.06,33.25) v3(71.06,32.29) v3(71.23,60.42) v3(71.16,58.99) v3(71.16,23.82) v3(71.23,22.38) v3(71.44,60.64) v3(71.37,59.2) v3(71.36,50.52) v3(71.36,49.56) v3(71.36,33.25) v3(71.36,32.28) v3(71.37,23.6) v3(71.44,22.17) v3(71.59,59.42) v3(71.59,23.39) v3(71.66,60.85) v3(71.67,50.52) v3(71.67,49.56) v3(71.67,33.25) v3(71.67,32.28) v3(71.66,21.95) v3(71.81,59.63) v3(71.81,23.17) v3(71.87,61.07) v3(71.87,21.74) v3(72.02,59.85) v3(71.97,50.52) v3(71.97,49.56) v3(71.97,33.25) v3(71.97,32.28) v3(72.02,22.95) v3(72.09,61.28) v3(72.09,21.52) v3(72.24,60.06) v3(72.24,22.74) v3(72.31,61.5) v3(72.28,50.52) v3(72.28,49.56) v3(72.28,33.25) v3(72.28,32.28) v3(72.31,21.31) v3(72.52,61.71) v3(72.45,60.28) v3(72.45,22.52) v3(72.52,21.09) v3(72.58,50.52) v3(72.58,49.56) v3(72.58,33.25) v3(72.58,32.28) v3(72.74,61.93) v3(72.67,60.5) v3(72.67,22.31) v3(72.74,20.87) v3(72.88,60.71) v3(72.89,50.52) v3(72.89,49.56) v3(72.89,33.25) v3(72.89,32.28) v3(72.88,22.09) v3(72.95,62.15) v3(72.95,20.66) v3(73.1,60.93) v3(73.1,21.88) v3(73.17,62.36) v3(73.19,50.52) v3(73.19,49.56) v3(73.19,33.25) v3(73.19,32.28) v3(73.17,20.44) v3(73.31,61.14) v3(73.31,21.66) v3(73.38,62.58) v3(73.38,20.23) v3(73.53,61.36) v3(73.5,50.52) v3(73.5,49.56) v3(73.5,33.25) v3(73.5,32.28) v3(73.53,21.45) v3(73.6,62.79) v3(73.6,20.01) v3(73.74,61.57) v3(73.74,21.23) v3(73.81,63.01) v3(73.8,50.52) v3(73.8,49.56) v3(73.8,33.25) v3(73.8,32.28) v3(73.81,19.8) v3(74.03,63.22) v3(73.96,61.79) v3(73.96,21.01) v3(74.03,19.58) v3(74.11,50.52) v3(74.11,49.56) v3(74.11,33.25) v3(74.11,32.28) v3(74.25,63.44) v3(74.18,62) v3(74.18,20.8) v3(74.25,19.37) v3(74.39,62.22) v3(74.41,50.52) v3(74.41,49.56) v3(74.41,33.25) v3(74.41,32.28) v3(74.39,20.58) v3(74.46,63.65) v3(74.46,19.15) v3(74.61,62.44) v3(74.61,20.37) v3(74.68,63.87) v3(74.72,50.52) v3(74.72,49.56) v3(74.72,33.25) v3(74.72,32.28) v3(74.68,18.93) v3(74.82,62.65) v3(74.82,20.15) v3(74.89,64.09) v3(74.89,18.72) v3(75.04,62.87) v3(75.02,50.52) v3(75.02,49.56) v3(75.02,33.25) v3(75.02,32.28) v3(75.04,19.94) v3(75.11,64.3) v3(75.11,18.5) v3(75.32,64.52) v3(75.25,63.08) v3(75.33,50.52) v3(75.33,49.56) v3(75.33,33.25) v3(75.33,32.28) v3(75.25,19.72) v3(75.32,18.29) v3(75.54,64.73) v3(75.47,63.3) v3(75.47,19.51) v3(75.54,18.07) v3(75.63,50.52) v3(75.63,49.56) v3(75.63,33.25) v3(75.63,32.28) v3(75.68,63.51) v3(75.68,19.29) v3(75.75,64.95) v3(75.75,17.86) v3(75.9,63.73) v3(75.94,50.52) v3(75.94,49.56) v3(75.94,33.25) v3(75.94,32.28) v3(75.9,19.08) v3(75.97,65.16) v3(75.97,17.64) v3(76.12,63.94) v3(76.12,18.86) v3(76.18,65.38) v3(76.24,50.52) v3(76.24,49.56) v3(76.24,33.25) v3(76.24,32.28) v3(76.18,17.43) v3(76.33,64.16) v3(76.33,18.64) v3(76.4,65.59) v3(76.4,17.21) v3(76.55,64.38) v3(76.55,50.52) v3(76.55,49.56) v3(76.55,33.25) v3(76.55,32.28) v3(76.55,18.43) v3(76.62,65.81) v3(76.62,16.99) v3(76.83,66.03) v3(76.76,64.59) v3(76.76,18.21) v3(76.83,16.78) v3(76.85,50.52) v3(76.85,49.56) v3(76.85,33.25) v3(76.85,32.28) v3(76.98,64.81) v3(76.98,18) v3(77.05,66.24) v3(77.05,16.56) v3(77.19,65.02) v3(77.15,50.52) v3(77.15,49.56) v3(77.15,33.25) v3(77.15,32.28) v3(77.19,17.78) v3(77.26,66.46) v3(77.26,16.35) v3(77.41,65.24) v3(77.41,17.57) v3(77.48,66.67) v3(77.46,50.52) v3(77.46,49.56) v3(77.46,33.25) v3(77.46,32.28) v3(77.48,16.13) v3(77.62,65.45) v3(77.62,17.35) v3(77.71,66.87) v3(77.71,15.93) v3(77.84,65.67) v3(77.76,50.52) v3(77.76,49.56) v3(77.76,33.25) v3(77.76,32.28) v3(77.84,17.14) v3(77.95,67.06) v3(77.95,15.74) v3(78.06,65.88) v3(78.07,50.52) v3(78.07,49.56) v3(78.07,33.25) v3(78.07,32.28) v3(78.06,16.92) v3(78.2,67.23) v3(78.2,15.58) v3(78.28,66.09) v3(78.28,16.71) v3(78.37,50.52) v3(78.37,49.56) v3(78.37,33.25) v3(78.37,32.28) v3(78.47,67.37) v3(78.52,66.28) v3(78.52,16.52) v3(78.47,15.43) v3(78.68,50.52) v3(78.68,49.56) v3(78.68,33.25) v3(78.68,32.28) v3(78.75,67.5) v3(78.78,66.44) v3(78.78,16.36) v3(78.75,15.31) v3(79.03,67.6) v3(78.98,50.52) v3(78.98,49.56) v3(78.98,33.25) v3(78.98,32.28) v3(79.03,15.2) v3(79.05,66.58) v3(79.05,16.23) v3(79.33,67.68) v3(79.33,66.68) v3(79.29,50.52) v3(79.29,49.56) v3(79.29,33.25) v3(79.29,32.28) v3(79.33,16.12) v3(79.33,15.12) v3(79.63,67.74) v3(79.63,66.76) v3(79.59,50.52) v3(79.59,49.56) v3(79.59,33.25) v3(79.59,32.28) v3(79.63,16.04) v3(79.63,15.06) v3(79.93,67.78) v3(79.93,66.81) v3(79.9,50.52) v3(79.9,49.56) v3(79.9,33.25) v3(79.9,32.28) v3(79.93,15.99) v3(79.93,15.02) v3(80.23,67.79) v3(80.23,66.83) v3(80.2,50.52) v3(80.2,49.56) v3(80.2,33.25) v3(80.2,32.28) v3(80.23,15.98) v3(80.23,15.01) v3(80.54,67.79) v3(80.54,66.83) v3(80.51,50.52) v3(80.51,49.56) v3(80.51,33.25) v3(80.51,32.28) v3(80.54,15.98) v3(80.54,15.01) v3(80.84,67.79) v3(80.84,66.83) v3(80.81,50.52) v3(80.81,49.56) v3(80.81,33.25) v3(80.81,32.28) v3(80.84,15.98) v3(80.84,15.01) v3(81.12,50.52) v3(81.12,49.56) v3(81.12,33.25) v3(81.12,32.28) v3(81.15,67.79) v3(81.15,66.83) v3(81.15,15.98) v3(81.15,15.01) v3(81.42,50.52) v3(81.42,49.56) v3(81.42,33.25) v3(81.42,32.28) v3(81.45,67.79) v3(81.45,66.83) v3(81.45,15.98) v3(81.45,15.01) v3(81.73,50.52) v3(81.73,49.56) v3(81.73,33.25) v3(81.73,32.28) v3(81.76,67.79) v3(81.76,66.83) v3(81.76,15.98) v3(81.76,15.01) v3(82.03,50.52) v3(82.03,49.56) v3(82.03,33.25) v3(82.03,32.28) v3(82.06,67.79) v3(82.06,66.83) v3(82.06,15.98) v3(82.06,15.01) v3(82.34,50.52) v3(82.34,49.56) v3(82.34,33.25) v3(82.34,32.28) v3(82.64,50.52) v3(82.64,49.56) v3(82.64,33.25) v3(82.64,32.28) v3(82.95,50.52) v3(82.95,49.56) v3(82.95,33.25) v3(82.95,32.28) v3(83.25,50.52) v3(83.25,49.56) v3(83.25,33.25) v3(83.25,32.28) v3(83.56,50.52) v3(83.56,49.56) v3(83.56,33.25) v3(83.56,32.28) v3(83.86,50.52) v3(83.86,49.56) v3(83.86,33.25) v3(83.86,32.28) v3(84.17,50.52) v3(84.17,49.56) v3(84.17,33.25) v3(84.17,32.28) v3(84.47,50.52) v3(84.47,49.56) v3(84.47,33.25) v3(84.47,32.28) v3(84.77,50.52) v3(84.77,49.56) v3(84.77,33.25) v3(84.77,32.28) v3(85.08,50.52) v3(85.08,49.56) v3(85.08,33.25) v3(85.08,32.28) v3(85.38,50.52) v3(85.38,49.56) v3(85.38,33.25) v3(85.38,32.28) v3(85.69,50.52) v3(85.69,49.56) v3(85.69,33.25) v3(85.69,32.28) v3(85.99,50.52) v3(85.99,49.56) v3(85.99,33.25) v3(85.99,32.28) v3(86.3,50.52) v3(86.3,49.56) v3(86.3,33.25) v3(86.3,32.28) v3(86.6,50.52) v3(86.6,49.56) v3(86.6,33.25) v3(86.6,32.28) v3(86.91,50.52) v3(86.91,49.56) v3(86.91,33.25) v3(86.91,32.28) v3(87.21,50.52) v3(87.21,49.56) v3(87.21,33.25) v3(87.21,32.28) v3(87.52,50.52) v3(87.52,49.56) v3(87.52,33.25) v3(87.52,32.28) v3(87.82,50.52) v3(87.82,49.56) v3(87.82,33.25) v3(87.82,32.28) v3(88.13,50.52) v3(88.13,49.56) v3(88.13,33.25) v3(88.13,32.28) v3(88.43,50.52) v3(88.43,49.56) v3(88.43,33.25) v3(88.43,32.28) v3(88.74,50.52) v3(88.74,49.56) v3(88.74,33.25) v3(88.74,32.28) v3(89.04,50.52) v3(89.04,49.56) v3(89.04,33.25) v3(89.04,32.28) v6(0.25,42.16) v6(2.16,40.26) v6(4.06,42.16) v6(5.97,40.26) v6(7.87,84.07) v6(7.87,80.26) v6(7.87,76.45) v6(7.87,57.4) v6(7.87,42.16) v6(7.87,23.11) v6(7.87,7.87) v6(7.87,4.06) v6(7.87,0.25) v6(9.78,78.36) v6(9.78,74.55) v6(9.78,59.31) v6(9.78,55.5) v6(9.78,51.69) v6(9.78,47.88) v6(9.78,44.07) v6(9.78,40.26) v6(9.78,36.45) v6(9.78,28.83) v6(9.78,25.02) v6(9.78,5.97) v6(11.68,76.45) v6(11.68,57.4) v6(11.68,53.59) v6(11.68,45.97) v6(11.68,42.16) v6(11.68,38.35) v6(11.68,34.54) v6(11.68,30.73) v6(11.68,26.92) v6(11.68,23.11) v6(11.68,7.87) v6(11.68,0.25) v6(13.59,78.36) v6(13.59,74.55) v6(13.59,59.31) v6(13.59,55.5) v6(13.59,51.69) v6(13.59,47.88) v6(13.59,44.07) v6(13.59,40.26) v6(13.59,36.45) v6(13.59,28.83) v6(13.59,25.02) v6(13.59,5.97) v6(13.59,2.16) v6(15.49,84.07) v6(15.49,76.45) v6(15.49,72.64) v6(15.49,68.83) v6(15.49,65.02) v6(15.49,61.21) v6(15.49,57.4) v6(15.49,53.59) v6(15.49,45.97) v6(15.49,42.16) v6(15.49,38.35) v6(15.49,34.54) v6(15.49,30.73) v6(15.49,26.92) v6(15.49,23.11) v6(15.49,19.3) v6(15.49,11.68) v6(15.49,7.87) v6(15.49,4.06) v6(15.49,0.25) v6(17.4,82.17) v6(17.4,78.36) v6(17.4,74.55) v6(17.4,70.74) v6(17.4,63.12) v6(17.4,59.31) v6(17.4,55.5) v6(17.4,51.69) v6(17.4,47.88) v6(17.4,44.07) v6(17.4,40.26) v6(17.4,36.45) v6(17.4,28.83) v6(17.4,25.02) v6(17.4,21.21) v6(17.4,17.4) v6(17.4,13.59) v6(17.4,9.78) v6(17.4,5.97) v6(17.4,2.16) v6(19.3,84.07) v6(19.3,76.45) v6(19.3,72.64) v6(19.3,68.83) v6(19.3,65.02) v6(19.3,61.21) v6(19.3,57.4) v6(19.3,53.59) v6(19.3,45.97) v6(19.3,42.16) v6(19.3,38.35) v6(19.3,34.54) v6(19.3,30.73) v6(19.3,26.92) v6(19.3,23.11) v6(19.3,19.3) v6(19.3,15.49) v6(19.3,11.68) v6(19.3,7.87) v6(19.3,4.06) v6(19.3,0.25) v6(21.21,78.36) v6(21.21,74.55) v6(21.21,70.74) v6(21.21,66.93) v6(21.21,63.12) v6(21.21,59.31) v6(21.21,55.5) v6(21.21,51.69) v6(21.21,47.88) v6(21.21,44.07) v6(21.21,40.26) v6(21.21,36.45) v6(21.21,28.83) v6(21.21,25.02) v6(21.21,21.21) v6(21.21,17.4) v6(21.21,13.59) v6(21.21,9.78) v6(21.21,5.97) v6(21.21,2.16) v6(23.11,84.07) v6(23.11,76.45) v6(23.11,72.64) v6(23.11,68.83) v6(23.11,65.02) v6(23.11,61.21) v6(23.11,57.4) v6(23.11,53.59) v6(23.11,45.97) v6(23.11,42.16) v6(23.11,38.35) v6(23.11,34.54) v6(23.11,30.73) v6(23.11,26.92) v6(23.11,23.11) v6(23.11,19.3) v6(23.11,15.49) v6(23.11,11.68) v6(23.11,7.87) v6(23.11,4.06) v6(23.11,0.25) v6(25.02,74.55) v6(25.02,70.74) v6(25.02,66.93) v6(25.02,63.12) v6(25.02,59.31) v6(25.02,55.5) v6(25.02,51.69) v6(25.02,47.88) v6(25.02,44.07) v6(25.02,40.26) v6(25.02,36.45) v6(25.02,28.83) v6(25.02,25.02) v6(25.02,21.21) v6(25.02,17.4) v6(25.02,13.59) v6(25.02,9.78) v6(25.02,5.97) v6(25.02,2.16) v6(26.92,76.45) v6(26.92,72.64) v6(26.92,68.83) v6(26.92,65.02) v6(26.92,61.21) v6(26.92,57.4) v6(26.92,53.59) v6(26.92,45.97) v6(26.92,42.16) v6(26.92,38.35) v6(26.92,34.54) v6(26.92,30.73) v6(26.92,26.92) v6(26.92,23.11) v6(26.92,19.3) v6(26.92,15.49) v6(26.92,11.68) v6(26.92,7.87) v6(26.92,4.06) v6(26.92,0.25) v6(28.83,82.17) v6(28.83,78.36) v6(28.83,74.55) v6(28.83,70.74) v6(28.83,66.93) v6(28.83,63.12) v6(28.83,59.31) v6(28.83,55.5) v6(28.83,51.69) v6(28.83,47.88) v6(28.83,44.07) v6(28.83,40.26) v6(28.83,36.45) v6(28.83,32.64) v6(28.83,28.83) v6(28.83,25.02) v6(28.83,21.21) v6(28.83,17.4) v6(28.83,13.59) v6(28.83,9.78) v6(28.83,5.97) v6(28.83,2.16) v6(30.73,84.07) v6(30.73,76.45) v6(30.73,72.64) v6(30.73,68.83) v6(30.73,65.02) v6(30.73,61.21) v6(30.73,57.4) v6(30.73,53.59) v6(30.73,49.78) v6(30.73,45.97) v6(30.73,42.16) v6(30.73,38.35) v6(30.73,30.73) v6(30.73,26.92) v6(30.73,23.11) v6(30.73,19.3) v6(30.73,15.49) v6(30.73,11.68) v6(30.73,7.87) v6(30.73,4.06) v6(30.73,0.25) v6(32.64,78.36) v6(32.64,74.55) v6(32.64,70.74) v6(32.64,66.93) v6(32.64,63.12) v6(32.64,59.31) v6(32.64,55.5) v6(32.64,51.69) v6(32.64,44.07) v6(32.64,40.26) v6(32.64,32.64) v6(32.64,28.83) v6(32.64,25.02) v6(32.64,21.21) v6(32.64,17.4) v6(32.64,13.59) v6(32.64,9.78) v6(34.54,84.07) v6(34.54,80.26) v6(34.54,76.45) v6(34.54,72.64) v6(34.54,68.83) v6(34.54,65.02) v6(34.54,61.21) v6(34.54,57.4) v6(34.54,53.59) v6(34.54,49.78) v6(34.54,42.16) v6(34.54,34.54) v6(34.54,30.73) v6(34.54,26.92) v6(34.54,23.11) v6(34.54,19.3) v6(34.54,15.49) v6(34.54,11.68) v6(36.45,74.55) v6(36.45,70.74) v6(36.45,66.93) v6(36.45,63.12) v6(36.45,59.31) v6(36.45,55.5) v6(36.45,51.69) v6(36.45,47.88) v6(36.45,36.45) v6(36.45,32.64) v6(36.45,28.83) v6(36.45,25.02) v6(36.45,21.21) v6(36.45,17.4) v6(36.45,13.59) v6(36.45,9.78) v6(38.35,84.07) v6(38.35,80.26) v6(38.35,76.45) v6(38.35,72.64) v6(38.35,68.83) v6(38.35,65.02) v6(38.35,61.21) v6(38.35,57.4) v6(38.35,53.59) v6(38.35,49.78) v6(38.35,45.97) v6(38.35,38.35) v6(38.35,34.54) v6(38.35,30.73) v6(38.35,26.92) v6(40.26,74.55) v6(40.26,70.74) v6(40.26,66.93) v6(40.26,63.12) v6(40.26,59.31) v6(40.26,51.69) v6(40.26,44.07) v6(40.26,36.45) v6(40.26,32.64) v6(40.26,28.83) v6(40.26,25.02) v6(40.26,21.21) v6(40.26,17.4) v6(40.26,13.59) v6(40.26,9.78) v6(42.16,84.07) v6(42.16,80.26) v6(42.16,76.45) v6(42.16,72.64) v6(42.16,68.83) v6(42.16,65.02) v6(42.16,61.21) v6(42.16,57.4) v6(42.16,53.59) v6(42.16,49.78) v6(42.16,34.54) v6(42.16,30.73) v6(42.16,26.92) v6(42.16,23.11) v6(42.16,19.3) v6(42.16,15.49) v6(42.16,11.68) v6(44.07,74.55) v6(44.07,70.74) v6(44.07,66.93) v6(44.07,63.12) v6(44.07,59.31) v6(44.07,51.69) v6(44.07,36.45) v6(44.07,32.64) v6(44.07,28.83) v6(44.07,25.02) v6(44.07,21.21) v6(44.07,17.4) v6(44.07,13.59) v6(44.07,9.78) v6(45.97,84.07) v6(45.97,80.26) v6(45.97,76.45) v6(45.97,72.64) v6(45.97,68.83) v6(45.97,65.02) v6(45.97,61.21) v6(45.97,57.4) v6(45.97,53.59) v6(45.97,49.78) v6(45.97,34.54) v6(45.97,30.73) v6(45.97,26.92) v6(45.97,23.11) v6(45.97,19.3) v6(45.97,15.49) v6(45.97,11.68) v6(45.97,7.87) v6(45.97,4.06) v6(45.97,0.25) v6(47.88,82.17) v6(47.88,32.64) v6(47.88,28.83) v6(47.88,25.02) v6(47.88,21.21) v6(47.88,17.4) v6(47.88,13.59) v6(47.88,9.78) v6(47.88,5.97) v6(47.88,2.16) v6(49.78,84.07) v6(49.78,72.64) v6(49.78,68.83) v6(49.78,65.02) v6(49.78,61.21) v6(49.78,57.4) v6(49.78,53.59) v6(49.78,30.73) v6(49.78,26.92) v6(49.78,23.11) v6(49.78,19.3) v6(49.78,15.49) v6(49.78,11.68) v6(49.78,7.87) v6(49.78,4.06) v6(49.78,0.25) v6(51.69,82.17) v6(51.69,74.55) v6(51.69,70.74) v6(51.69,66.93) v6(51.69,63.12) v6(51.69,59.31) v6(51.69,51.69) v6(51.69,28.83) v6(51.69,25.02) v6(51.69,21.21) v6(51.69,17.4) v6(51.69,13.59) v6(51.69,9.78) v6(51.69,5.97) v6(51.69,2.16) v6(53.59,84.07) v6(53.59,76.45) v6(53.59,34.54) v6(53.59,26.92) v6(53.59,23.11) v6(53.59,19.3) v6(53.59,15.49) v6(53.59,11.68) v6(53.59,7.87) v6(55.5,82.17) v6(55.5,78.36) v6(55.5,70.74) v6(55.5,66.93) v6(55.5,63.12) v6(55.5,59.31) v6(55.5,55.5) v6(55.5,36.45) v6(55.5,32.64) v6(55.5,25.02) v6(55.5,21.21) v6(55.5,17.4) v6(55.5,13.59) v6(55.5,9.78) v6(57.4,72.64) v6(57.4,68.83) v6(57.4,65.02) v6(57.4,61.21) v6(57.4,57.4) v6(57.4,53.59) v6(57.4,49.78) v6(57.4,38.35) v6(57.4,34.54) v6(57.4,30.73) v6(57.4,23.11) v6(57.4,19.3) v6(57.4,15.49) v6(57.4,11.68) v6(59.31,82.17) v6(59.31,74.55) v6(59.31,70.74) v6(59.31,66.93) v6(59.31,63.12) v6(59.31,59.31) v6(59.31,55.5) v6(59.31,51.69) v6(59.31,44.07) v6(59.31,36.45) v6(59.31,32.64) v6(59.31,28.83) v6(61.21,76.45) v6(61.21,72.64) v6(61.21,68.83) v6(61.21,65.02) v6(61.21,61.21) v6(61.21,57.4) v6(61.21,53.59) v6(61.21,45.97) v6(61.21,42.16) v6(61.21,38.35) v6(61.21,34.54) v6(61.21,30.73) v6(61.21,26.92) v6(61.21,23.11) v6(61.21,19.3) v6(61.21,15.49) v6(61.21,11.68) v6(63.12,59.31) v6(63.12,55.5) v6(63.12,47.88) v6(63.12,40.26) v6(63.12,36.45) v6(63.12,32.64) v6(63.12,28.83) v6(63.12,25.02) v6(63.12,21.21) v6(63.12,17.4) v6(63.12,13.59) v6(63.12,9.78) v6(65.02,76.45) v6(65.02,72.64) v6(65.02,68.83) v6(65.02,65.02) v6(65.02,61.21) v6(65.02,57.4) v6(65.02,49.78) v6(65.02,42.16) v6(65.02,38.35) v6(65.02,34.54) v6(65.02,30.73) v6(65.02,26.92) v6(65.02,23.11) v6(65.02,19.3) v6(65.02,15.49) v6(65.02,11.68) v6(65.02,7.87) v6(66.93,82.17) v6(66.93,74.55) v6(66.93,63.12) v6(66.93,59.31) v6(66.93,51.69) v6(66.93,44.07) v6(66.93,40.26) v6(66.93,36.45) v6(66.93,32.64) v6(66.93,28.83) v6(66.93,25.02) v6(66.93,21.21) v6(66.93,17.4) v6(66.93,13.59) v6(66.93,9.78) v6(66.93,5.97) v6(66.93,2.16) v6(68.83,76.45) v6(68.83,72.64) v6(68.83,65.02) v6(68.83,61.21) v6(68.83,53.59) v6(68.83,45.97) v6(68.83,42.16) v6(68.83,38.35) v6(68.83,34.54) v6(68.83,30.73) v6(68.83,26.92) v6(68.83,23.11) v6(68.83,19.3) v6(68.83,15.49) v6(68.83,11.68) v6(68.83,7.87) v6(68.83,4.06) v6(68.83,0.25) v6(70.74,74.55) v6(70.74,70.74) v6(70.74,63.12) v6(70.74,55.5) v6(70.74,51.69) v6(70.74,47.88) v6(70.74,44.07) v6(70.74,40.26) v6(70.74,36.45) v6(70.74,28.83) v6(70.74,25.02) v6(70.74,21.21) v6(70.74,17.4) v6(70.74,13.59) v6(70.74,9.78) v6(70.74,5.97) v6(70.74,2.16) v6(72.64,68.83) v6(72.64,65.02) v6(72.64,57.4) v6(72.64,53.59) v6(72.64,45.97) v6(72.64,42.16) v6(72.64,38.35) v6(72.64,34.54) v6(72.64,30.73) v6(72.64,26.92) v6(72.64,23.11) v6(72.64,19.3) v6(72.64,15.49) v6(72.64,11.68) v6(72.64,7.87) v6(72.64,4.06) v6(72.64,0.25) v6(74.55,82.17) v6(74.55,74.55) v6(74.55,70.74) v6(74.55,66.93) v6(74.55,59.31) v6(74.55,55.5) v6(74.55,51.69) v6(74.55,47.88) v6(74.55,44.07) v6(74.55,40.26) v6(74.55,36.45) v6(74.55,28.83) v6(74.55,25.02) v6(74.55,21.21) v6(74.55,17.4) v6(74.55,13.59) v6(74.55,9.78) v6(74.55,5.97) v6(74.55,2.16) v6(76.45,72.64) v6(76.45,68.83) v6(76.45,61.21) v6(76.45,57.4) v6(76.45,53.59) v6(76.45,45.97) v6(76.45,42.16) v6(76.45,38.35) v6(76.45,34.54) v6(76.45,30.73) v6(76.45,26.92) v6(76.45,23.11) v6(76.45,19.3) v6(76.45,15.49) v6(76.45,11.68) v6(76.45,7.87) v6(76.45,4.06) v6(76.45,0.25) v6(78.36,78.36) v6(78.36,74.55) v6(78.36,70.74) v6(78.36,63.12) v6(78.36,59.31) v6(78.36,55.5) v6(78.36,51.69) v6(78.36,47.88) v6(78.36,44.07) v6(78.36,40.26) v6(78.36,36.45) v6(78.36,28.83) v6(78.36,25.02) v6(78.36,21.21) v6(78.36,17.4) v6(78.36,13.59) v6(78.36,9.78) v6(78.36,5.97) v6(78.36,2.16) v6(80.26,76.45) v6(80.26,72.64) v6(80.26,68.83) v6(80.26,65.02) v6(80.26,61.21) v6(80.26,57.4) v6(80.26,53.59) v6(80.26,45.97) v6(80.26,42.16) v6(80.26,38.35) v6(80.26,34.54) v6(80.26,30.73) v6(80.26,26.92) v6(80.26,23.11) v6(80.26,19.3) v6(80.26,11.68) v6(80.26,7.87) v6(80.26,4.06) v6(80.26,0.25) v6(82.17,82.17) v6(82.17,78.36) v6(82.17,74.55) v6(82.17,70.74) v6(82.17,63.12) v6(82.17,59.31) v6(82.17,55.5) v6(82.17,51.69) v6(82.17,47.88) v6(82.17,44.07) v6(82.17,40.26) v6(82.17,36.45) v6(82.17,28.83) v6(82.17,25.02) v6(82.17,21.21) v6(82.17,17.4) v6(82.17,13.59) v6(82.17,9.78) v6(82.17,5.97) v6(82.17,2.16) v6(84.07,80.26) v6(84.07,76.45) v6(84.07,57.4) v6(84.07,53.59) v6(84.07,45.97) v6(84.07,42.16) v6(84.07,38.35) v6(84.07,34.54) v6(84.07,30.73) v6(84.07,26.92) v6(84.07,23.11) v6(84.07,7.87) v6(84.07,0.25) v6(85.98,78.36) v6(85.98,74.55) v6(85.98,59.31) v6(85.98,55.5) v6(85.98,51.69) v6(85.98,47.88) v6(85.98,44.07) v6(85.98,40.26) v6(85.98,36.45) v6(85.98,28.83) v6(85.98,25.02) v6(87.88,84.07) v6(87.88,80.26) v6(87.88,76.45) v6(87.88,57.4) v6(87.88,53.59) v6(87.88,45.97) v6(87.88,42.16) v6(87.88,38.35) v6(87.88,34.54) v6(87.88,30.73) v6(87.88,26.92) v6(87.88,23.11) v6(87.88,7.87) v6(87.88,0.25) v6(89.79,82.17) v6(89.79,78.36) v6(89.79,74.55) v6(89.79,59.31) v6(89.79,40.26) v6(89.79,25.02) v6(89.79,5.97) v6(89.79,2.16) v6(91.69,42.16) v6(93.6,40.26) v6(95.5,42.16) v7(0.17,56.23) v7(0.15,55.37) v7(0.15,54.46) v7(0.15,53.54) v7(0.15,52.63) v7(0.15,51.71) v7(0.15,51.1) v7(0.15,50.68) v7(0.15,49.39) v7(0.15,48.97) v7(0.15,48.36) v7(0.15,47.45) v7(0.15,46.53) v7(0.15,45.62) v7(0.15,44.7) v7(0.16,43.85) v7(0.17,38.96) v7(0.15,38.1) v7(0.15,37.19) v7(0.15,36.27) v7(0.15,35.36) v7(0.15,34.44) v7(0.15,33.83) v7(0.15,33.41) v7(0.15,32.12) v7(0.15,31.7) v7(0.15,31.09) v7(0.15,30.18) v7(0.15,29.26) v7(0.15,28.34) v7(0.15,27.43) v7(0.16,26.58) v7(0.46,51.11) v7(0.46,50.69) v7(0.46,49.39) v7(0.46,48.97) v7(0.46,33.83) v7(0.46,33.41) v7(0.46,32.12) v7(0.46,31.7) v7(0.76,51.1) v7(0.76,50.61) v7(0.76,49.47) v7(0.76,48.97) v7(0.76,33.83) v7(0.76,33.34) v7(0.76,32.19) v7(0.76,31.7) v7(1.08,56.23) v7(1.07,55.37) v7(1.07,54.46) v7(1.06,53.54) v7(1.07,52.63) v7(1.07,51.71) v7(1.07,51.1) v7(1.07,50.61) v7(1.07,49.47) v7(1.07,48.97) v7(1.07,48.36) v7(1.07,47.45) v7(1.06,46.53) v7(1.07,45.62) v7(1.07,44.7) v7(1.07,43.85) v7(1.08,38.96) v7(1.07,38.1) v7(1.07,37.18) v7(1.06,36.27) v7(1.07,35.36) v7(1.07,34.44) v7(1.07,33.83) v7(1.07,33.34) v7(1.07,32.19) v7(1.07,31.7) v7(1.07,31.09) v7(1.07,30.18) v7(1.06,29.26) v7(1.07,28.35) v7(1.07,27.43) v7(1.07,26.58) v7(1.37,51.1) v7(1.37,50.5) v7(1.37,49.58) v7(1.37,48.97) v7(1.37,33.83) v7(1.37,33.22) v7(1.37,32.31) v7(1.37,31.7) v7(1.68,51.1) v7(1.67,50.5) v7(1.67,49.58) v7(1.68,48.97) v7(1.68,33.83) v7(1.67,33.22) v7(1.67,32.31) v7(1.68,31.7) v7(2,56.23) v7(1.98,53.54) v7(1.98,52.63) v7(1.98,51.71) v7(1.98,51.1) v7(1.98,50.5) v7(1.98,49.58) v7(1.98,48.97) v7(1.98,48.36) v7(1.98,47.45) v7(1.98,46.53) v7(1.99,43.85) v7(2,38.96) v7(1.98,36.27) v7(1.98,35.36) v7(1.98,34.44) v7(1.98,33.83) v7(1.98,33.22) v7(1.98,32.31) v7(1.98,31.7) v7(1.98,31.09) v7(1.98,30.18) v7(1.98,29.26) v7(1.99,26.58) v7(2.29,51.1) v7(2.28,50.5) v7(2.28,49.58) v7(2.28,48.97) v7(2.29,33.83) v7(2.28,33.22) v7(2.28,32.31) v7(2.28,31.7) v7(2.59,51.1) v7(2.59,50.5) v7(2.59,49.58) v7(2.59,48.97) v7(2.59,33.83) v7(2.59,33.22) v7(2.59,32.31) v7(2.59,31.7) v7(2.89,52.63) v7(2.9,51.71) v7(2.89,51.1) v7(2.89,50.5) v7(2.9,49.58) v7(2.89,48.97) v7(2.89,48.36) v7(2.89,47.45) v7(2.89,35.36) v7(2.9,34.44) v7(2.89,33.83) v7(2.89,33.22) v7(2.9,32.31) v7(2.89,31.7) v7(2.89,31.09) v7(2.89,30.18) v7(3.2,51.1) v7(3.22,50.53) v7(3.22,49.54) v7(3.2,48.97) v7(3.2,33.83) v7(3.22,33.26) v7(3.22,32.27) v7(3.2,31.7) v7(3.5,51.11) v7(3.51,50.61) v7(3.5,49.46) v7(3.5,48.97) v7(3.5,33.83) v7(3.51,33.34) v7(3.5,32.19) v7(3.5,31.7) v7(3.82,56.23) v7(3.81,53.54) v7(3.81,52.63) v7(3.81,51.71) v7(3.81,51.11) v7(3.8,50.54) v7(3.8,49.53) v7(3.81,48.97) v7(3.81,48.36) v7(3.81,47.45) v7(3.81,46.53) v7(3.81,43.85) v7(3.82,38.96) v7(3.81,36.27) v7(3.81,35.36) v7(3.81,34.44) v7(3.81,33.83) v7(3.79,33.26) v7(3.8,32.26) v7(3.81,31.7) v7(3.81,31.09) v7(3.81,30.18) v7(3.81,29.26) v7(3.81,26.58) v7(4.11,51.11) v7(4.1,50.55) v7(4.1,49.53) v7(4.11,48.97) v7(4.11,33.83) v7(4.1,33.27) v7(4.1,32.26) v7(4.11,31.7) v7(4.42,51.11) v7(4.41,50.55) v7(4.41,49.53) v7(4.42,48.97) v7(4.42,33.83) v7(4.41,33.27) v7(4.41,32.26) v7(4.42,31.7) v7(4.74,56.23) v7(4.72,55.37) v7(4.72,54.46) v7(4.72,53.54) v7(4.72,52.63) v7(4.72,51.71) v7(4.72,51.11) v7(4.71,50.55) v7(4.71,49.53) v7(4.72,48.97) v7(4.72,48.36) v7(4.72,47.45) v7(4.72,46.53) v7(4.72,45.62) v7(4.72,44.7) v7(4.73,43.85) v7(4.74,38.96) v7(4.72,38.1) v7(4.72,37.19) v7(4.72,36.27) v7(4.72,35.36) v7(4.72,34.44) v7(4.72,33.83) v7(4.71,33.27) v7(4.71,32.26) v7(4.72,31.7) v7(4.72,31.09) v7(4.72,30.18) v7(4.72,29.26) v7(4.72,28.35) v7(4.72,27.43) v7(4.73,26.58) v7(5.03,51.11) v7(5.02,50.55) v7(5.02,49.53) v7(5.03,48.97) v7(5.03,33.83) v7(5.02,33.27) v7(5.02,32.26) v7(5.03,31.7) v7(5.33,51.11) v7(5.32,50.55) v7(5.32,49.53) v7(5.33,48.97) v7(5.33,33.83) v7(5.32,33.27) v7(5.32,32.26) v7(5.33,31.7) v7(5.64,55.37) v7(5.64,54.46) v7(5.64,53.54) v7(5.64,52.63) v7(5.64,51.71) v7(5.64,51.11) v7(5.63,50.55) v7(5.63,49.53) v7(5.64,48.97) v7(5.64,48.36) v7(5.64,47.45) v7(5.64,46.53) v7(5.64,45.62) v7(5.64,44.7) v7(5.64,43.85) v7(5.64,38.1) v7(5.64,37.19) v7(5.64,36.27) v7(5.64,35.36) v7(5.64,34.44) v7(5.64,33.83) v7(5.63,33.27) v7(5.63,32.26) v7(5.64,31.7) v7(5.64,31.09) v7(5.64,30.18) v7(5.64,29.26) v7(5.64,28.35) v7(5.64,27.43) v7(5.64,26.58) v7(5.65,56.23) v7(5.65,38.96) v7(5.94,51.11) v7(5.93,50.55) v7(5.93,49.53) v7(5.94,48.97) v7(5.94,33.83) v7(5.93,33.27) v7(5.93,32.26) v7(5.94,31.7) v7(6.25,51.11) v7(6.23,50.55) v7(6.23,49.53) v7(6.25,33.83) v7(6.23,33.27) v7(6.23,32.26) v7(6.25,48.97) v7(6.25,31.7) v7(6.54,50.55) v7(6.54,49.53) v7(6.54,33.27) v7(6.54,32.26) v7(6.57,56.23) v7(6.55,55.37) v7(6.55,54.46) v7(6.55,53.54) v7(6.55,52.63) v7(6.55,51.71) v7(6.55,51.11) v7(6.55,48.97) v7(6.55,48.36) v7(6.55,47.45) v7(6.55,46.53) v7(6.55,45.62) v7(6.55,44.7) v7(6.56,43.85) v7(6.57,38.96) v7(6.55,38.1) v7(6.55,37.19) v7(6.55,36.27) v7(6.55,35.36) v7(6.55,34.44) v7(6.55,33.83) v7(6.55,31.7) v7(6.55,31.09) v7(6.55,30.18) v7(6.55,29.26) v7(6.55,28.35) v7(6.55,27.43) v7(6.56,26.58) v7(6.84,50.55) v7(6.84,49.53) v7(6.84,33.27) v7(6.84,32.26) v7(6.86,51.11) v7(6.86,48.97) v7(6.86,33.83) v7(6.86,31.7) v7(7.13,73.5) v7(7.12,72.64) v7(7.12,71.73) v7(7.12,70.82) v7(7.12,69.9) v7(7.12,68.99) v7(7.12,68.38) v7(7.12,67.96) v7(7.12,66.66) v7(7.12,66.24) v7(7.12,65.63) v7(7.12,64.72) v7(7.12,63.81) v7(7.12,62.89) v7(7.12,61.97) v7(7.12,61.12) v7(7.13,21.69) v7(7.12,20.83) v7(7.12,19.91) v7(7.12,19) v7(7.12,18.08) v7(7.12,17.17) v7(7.12,16.56) v7(7.12,16.14) v7(7.12,14.85) v7(7.12,14.43) v7(7.12,13.82) v7(7.12,12.9) v7(7.12,11.99) v7(7.12,11.07) v7(7.12,10.16) v7(7.12,9.31) v7(7.16,51.11) v7(7.15,50.55) v7(7.15,49.53) v7(7.16,48.97) v7(7.16,33.83) v7(7.15,33.27) v7(7.15,32.26) v7(7.16,31.7) v7(7.42,68.38) v7(7.42,67.96) v7(7.42,66.66) v7(7.42,66.24) v7(7.41,50.71) v7(7.41,49.37) v7(7.41,33.44) v7(7.41,32.1) v7(7.42,16.56) v7(7.42,16.14) v7(7.42,14.85) v7(7.42,14.43) v7(7.48,56.24) v7(7.47,55.37) v7(7.47,54.46) v7(7.46,53.54) v7(7.47,52.63) v7(7.47,51.71) v7(7.47,51.11) v7(7.47,48.97) v7(7.47,48.36) v7(7.47,47.45) v7(7.47,46.53) v7(7.46,45.62) v7(7.47,44.7) v7(7.47,43.85) v7(7.48,38.96) v7(7.47,38.1) v7(7.47,37.19) v7(7.46,36.27) v7(7.47,35.36) v7(7.47,34.44) v7(7.47,33.83) v7(7.47,31.7) v7(7.47,31.09) v7(7.47,30.18) v7(7.47,29.26) v7(7.46,28.35) v7(7.47,27.43) v7(7.47,26.58) v7(7.73,68.38) v7(7.73,67.88) v7(7.73,66.74) v7(7.73,66.24) v7(7.73,16.56) v7(7.73,16.07) v7(7.73,14.92) v7(7.73,14.43) v7(8.03,72.64) v7(8.03,71.73) v7(8.03,70.81) v7(8.03,69.9) v7(8.03,68.99) v7(8.03,68.38) v7(8.03,67.88) v7(8.03,66.74) v7(8.03,66.24) v7(8.03,65.63) v7(8.03,64.72) v7(8.03,63.8) v7(8.03,62.89) v7(8.03,61.98) v7(8.04,61.12) v7(8.03,20.83) v7(8.03,19.91) v7(8.03,19) v7(8.03,18.08) v7(8.03,17.17) v7(8.03,16.56) v7(8.03,16.07) v7(8.03,14.92) v7(8.03,14.43) v7(8.03,13.82) v7(8.03,12.9) v7(8.03,11.99) v7(8.03,11.07) v7(8.03,10.16) v7(8.04,9.31) v7(8.05,73.5) v7(8.05,21.69) v7(8.34,68.38) v7(8.34,67.77) v7(8.34,66.85) v7(8.34,66.24) v7(8.34,16.56) v7(8.34,15.95) v7(8.34,15.04) v7(8.34,14.43) v7(8.64,68.38) v7(8.64,67.77) v7(8.64,66.85) v7(8.64,66.24) v7(8.64,16.56) v7(8.64,15.95) v7(8.64,15.04) v7(8.64,14.43) v7(8.95,67.77) v7(8.95,66.85) v7(8.95,63.8) v7(8.95,15.95) v7(8.95,15.04) v7(8.95,11.99) v7(8.96,73.5) v7(8.95,70.81) v7(8.95,69.9) v7(8.95,68.99) v7(8.95,68.38) v7(8.95,66.24) v7(8.95,65.63) v7(8.95,64.72) v7(8.95,61.12) v7(8.96,21.69) v7(8.95,19) v7(8.95,18.08) v7(8.95,17.17) v7(8.95,16.56) v7(8.95,14.43) v7(8.95,13.82) v7(8.95,12.9) v7(8.95,9.31) v7(9.25,68.38) v7(9.25,67.77) v7(9.25,66.85) v7(9.25,66.24) v7(9.25,16.56) v7(9.25,15.95) v7(9.25,15.04) v7(9.25,14.43) v7(9.56,68.38) v7(9.56,67.77) v7(9.56,66.85) v7(9.56,66.24) v7(9.56,16.56) v7(9.56,15.95) v7(9.56,15.04) v7(9.56,14.43) v7(9.86,69.9) v7(9.86,68.99) v7(9.86,68.38) v7(9.86,67.77) v7(9.87,66.85) v7(9.86,66.24) v7(9.86,65.63) v7(9.86,64.72) v7(9.86,18.08) v7(9.86,17.17) v7(9.86,16.56) v7(9.86,15.95) v7(9.86,15.04) v7(9.86,14.43) v7(9.86,13.82) v7(9.86,12.9) v7(10.17,68.38) v7(10.19,67.8) v7(10.19,66.82) v7(10.17,66.24) v7(10.17,16.56) v7(10.19,15.99) v7(10.19,15) v7(10.17,14.43) v7(10.47,68.38) v7(10.47,67.88) v7(10.47,66.74) v7(10.47,66.24) v7(10.47,16.56) v7(10.47,16.06) v7(10.47,14.92) v7(10.47,14.43) v7(10.79,73.5) v7(10.78,70.82) v7(10.78,69.9) v7(10.78,68.99) v7(10.78,68.38) v7(10.77,67.82) v7(10.76,66.8) v7(10.78,66.24) v7(10.78,65.63) v7(10.78,64.72) v7(10.78,63.8) v7(10.78,61.12) v7(10.79,21.69) v7(10.78,19) v7(10.78,18.08) v7(10.78,17.17) v7(10.78,16.56) v7(10.77,15.99) v7(10.76,14.99) v7(10.78,14.43) v7(10.78,13.82) v7(10.78,12.9) v7(10.78,11.99) v7(10.78,9.31) v7(11.08,68.38) v7(11.07,67.82) v7(11.07,66.8) v7(11.08,66.24) v7(11.08,16.56) v7(11.07,16) v7(11.07,14.99) v7(11.08,14.43) v7(11.39,68.38) v7(11.37,67.82) v7(11.37,66.8) v7(11.39,66.24) v7(11.39,16.56) v7(11.37,16) v7(11.37,14.99) v7(11.39,14.43) v7(11.71,73.5) v7(11.69,72.65) v7(11.69,71.73) v7(11.69,70.82) v7(11.69,69.9) v7(11.69,68.99) v7(11.69,68.38) v7(11.68,67.82) v7(11.68,66.8) v7(11.69,66.24) v7(11.69,65.63) v7(11.69,64.72) v7(11.69,63.8) v7(11.69,62.89) v7(11.69,61.98) v7(11.7,61.12) v7(11.71,21.69) v7(11.69,20.83) v7(11.69,19.91) v7(11.69,19) v7(11.69,18.08) v7(11.69,17.17) v7(11.69,16.56) v7(11.68,16) v7(11.68,14.99) v7(11.69,14.43) v7(11.69,13.82) v7(11.69,12.9) v7(11.69,11.99) v7(11.69,11.08) v7(11.69,10.16) v7(11.7,9.31) v7(12,68.38) v7(11.98,67.82) v7(11.98,66.8) v7(12,66.24) v7(12,16.56) v7(11.98,16) v7(11.98,14.99) v7(12,14.43) v7(12.3,68.38) v7(12.29,67.82) v7(12.29,66.8) v7(12.3,66.24) v7(12.3,16.56) v7(12.29,16) v7(12.29,14.99) v7(12.3,14.43) v7(12.62,73.5) v7(12.61,72.65) v7(12.61,71.73) v7(12.61,70.82) v7(12.61,69.9) v7(12.61,68.99) v7(12.6,68.38) v7(12.59,67.82) v7(12.59,66.8) v7(12.61,66.24) v7(12.61,65.63) v7(12.61,64.72) v7(12.61,63.8) v7(12.6,62.89) v7(12.61,61.98) v7(12.61,61.12) v7(12.62,21.69) v7(12.61,20.83) v7(12.61,19.91) v7(12.61,19) v7(12.61,18.08) v7(12.61,17.17) v7(12.6,16.56) v7(12.59,16) v7(12.59,14.99) v7(12.61,14.43) v7(12.61,13.82) v7(12.61,12.9) v7(12.61,11.99) v7(12.6,11.08) v7(12.61,10.16) v7(12.61,9.31) v7(12.91,68.38) v7(12.9,67.82) v7(12.9,66.8) v7(12.91,66.24) v7(12.91,16.56) v7(12.9,16) v7(12.9,14.99) v7(12.91,14.43) v7(13.21,68.38) v7(13.2,67.82) v7(13.2,66.8) v7(13.21,66.24) v7(13.21,16.56) v7(13.2,16) v7(13.2,14.99) v7(13.21,14.43) v7(13.54,73.5) v7(13.52,72.65) v7(13.52,71.73) v7(13.52,70.82) v7(13.52,69.9) v7(13.52,68.99) v7(13.52,68.38) v7(13.51,67.82) v7(13.51,66.8) v7(13.52,66.24) v7(13.52,65.63) v7(13.52,64.72) v7(13.52,63.8) v7(13.52,62.89) v7(13.52,61.98) v7(13.53,61.12) v7(13.54,21.69) v7(13.52,20.83) v7(13.52,19.91) v7(13.52,19) v7(13.52,18.08) v7(13.52,17.17) v7(13.52,16.56) v7(13.51,16) v7(13.51,14.99) v7(13.52,14.43) v7(13.52,13.82) v7(13.52,12.9) v7(13.52,11.99) v7(13.52,11.08) v7(13.52,10.16) v7(13.53,9.31) v7(13.82,68.38) v7(13.81,67.82) v7(13.81,66.8) v7(13.82,66.24) v7(13.82,16.56) v7(13.81,16) v7(13.81,14.99) v7(13.82,14.43) v7(14.13,68.38) v7(14.12,67.82) v7(14.12,66.8) v7(14.13,66.24) v7(14.13,16.56) v7(14.12,16) v7(14.12,14.99) v7(14.13,14.43) v7(14.44,73.51) v7(14.43,72.65) v7(14.43,71.73) v7(14.43,70.81) v7(14.43,69.9) v7(14.43,68.99) v7(14.43,68.38) v7(14.38,67.98) v7(14.38,66.65) v7(14.44,66.24) v7(14.43,65.63) v7(14.43,64.72) v7(14.43,63.8) v7(14.43,62.89) v7(14.44,61.98) v7(14.44,61.12) v7(14.44,21.69) v7(14.43,20.83) v7(14.43,19.91) v7(14.43,19) v7(14.43,18.08) v7(14.43,17.17) v7(14.43,16.56) v7(14.38,16.16) v7(14.38,14.83) v7(14.44,14.43) v7(14.43,13.82) v7(14.43,12.9) v7(14.43,11.99) v7(14.43,11.08) v7(14.44,10.16) v7(14.44,9.31) v7(32.14,7.48) v7(32.14,6.57) v7(32.14,5.65) v7(32.14,4.74) v7(32.14,3.82) v7(32.14,2) v7(32.14,1.08) v7(32.14,0.17) v7(33,7.47) v7(33,6.55) v7(33,5.64) v7(33,4.72) v7(33,1.07) v7(33,0.15) v7(33.92,7.47) v7(33.92,6.55) v7(33.92,5.64) v7(33.92,4.72) v7(33.92,1.07) v7(33.92,0.15) v7(34.83,7.46) v7(34.83,6.55) v7(34.83,5.64) v7(34.83,4.72) v7(34.83,3.81) v7(34.83,1.98) v7(34.83,1.06) v7(34.83,0.15) v7(35.75,7.47) v7(35.75,6.55) v7(35.75,5.64) v7(35.75,4.72) v7(35.75,3.81) v7(35.75,2.89) v7(35.75,1.98) v7(35.75,1.07) v7(35.75,0.15) v7(36.66,7.47) v7(36.66,6.55) v7(36.66,5.64) v7(36.66,4.72) v7(36.66,3.81) v7(36.66,2.9) v7(36.66,1.98) v7(36.66,1.07) v7(36.66,0.15) v7(37.27,7.47) v7(37.27,7.16) v7(37.27,6.86) v7(37.27,6.55) v7(37.27,6.25) v7(37.27,5.94) v7(37.27,5.64) v7(37.27,5.33) v7(37.27,5.03) v7(37.27,4.72) v7(37.27,4.42) v7(37.27,4.11) v7(37.27,3.81) v7(37.27,3.5) v7(37.27,3.2) v7(37.27,2.89) v7(37.27,2.59) v7(37.27,2.29) v7(37.27,1.98) v7(37.27,1.68) v7(37.27,1.37) v7(37.27,1.07) v7(37.27,0.76) v7(37.27,0.46) v7(37.27,0.15) v7(37.59,7.65) v7(37.69,0.46) v7(37.69,0.15) v7(37.83,7.46) v7(37.83,7.15) v7(37.83,6.84) v7(37.83,6.54) v7(37.83,6.23) v7(37.83,5.93) v7(37.83,5.63) v7(37.83,5.32) v7(37.83,5.02) v7(37.83,4.71) v7(37.83,4.41) v7(37.83,4.1) v7(37.83,3.8) v7(37.77,3.51) v7(37.84,3.22) v7(37.77,1.07) v7(37.77,0.76) v7(37.88,2.89) v7(37.88,2.59) v7(37.88,2.28) v7(37.88,1.98) v7(37.88,1.67) v7(37.88,1.37) v7(38.84,7.15) v7(38.84,6.84) v7(38.84,6.54) v7(38.84,6.23) v7(38.84,5.93) v7(38.84,5.63) v7(38.84,5.32) v7(38.84,5.02) v7(38.84,4.71) v7(38.84,4.41) v7(38.84,4.1) v7(38.84,3.8) v7(38.83,3.22) v7(38.8,2.9) v7(38.8,2.59) v7(38.8,2.28) v7(38.8,1.98) v7(38.8,1.67) v7(38.8,1.37) v7(38.85,7.45) v7(38.91,3.5) v7(38.91,1.07) v7(38.91,0.76) v7(38.98,0.46) v7(38.98,0.15) v7(39.08,7.66) v7(39.4,7.47) v7(39.4,7.16) v7(39.4,6.86) v7(39.4,6.55) v7(39.4,6.25) v7(39.4,5.94) v7(39.4,5.64) v7(39.4,5.33) v7(39.4,5.03) v7(39.4,4.72) v7(39.4,4.42) v7(39.4,4.11) v7(39.4,3.81) v7(39.4,3.5) v7(39.4,3.2) v7(39.4,2.89) v7(39.4,2.59) v7(39.4,2.28) v7(39.4,1.98) v7(39.4,1.68) v7(39.4,1.37) v7(39.4,1.07) v7(39.4,0.76) v7(39.4,0.46) v7(39.4,0.15) v7(39.99,42.39) v7(40.01,7.47) v7(40.01,6.55) v7(40.01,5.64) v7(40.01,4.72) v7(40.01,3.81) v7(40.01,2.89) v7(40.01,1.98) v7(40.01,1.07) v7(40.01,0.15) v7(40.29,42.39) v7(40.6,42.39) v7(40.9,42.39) v7(40.9,41.4) v7(40.93,7.47) v7(40.93,6.55) v7(40.93,5.64) v7(40.93,4.72) v7(40.93,3.81) v7(40.93,2.89) v7(40.93,1.98) v7(40.93,1.07) v7(40.93,0.15) v7(41.21,41.4) v7(41.51,41.4) v7(41.82,41.4) v7(41.84,7.47) v7(41.84,6.55) v7(41.84,5.64) v7(41.84,4.72) v7(41.84,3.81) v7(41.84,1.98) v7(41.84,1.06) v7(41.84,0.15) v7(42.12,40.41) v7(42.43,40.41) v7(42.73,40.41) v7(42.78,39.95) v7(42.76,7.46) v7(42.76,6.55) v7(42.76,5.64) v7(42.76,4.72) v7(42.76,1.07) v7(42.76,0.15) v7(43.04,40.41) v7(43.06,40.06) v7(43.34,40.41) v7(43.34,40.13) v7(43.65,40.41) v7(43.72,38.58) v7(43.67,7.47) v7(43.67,6.55) v7(43.67,5.64) v7(43.67,4.72) v7(43.67,1.07) v7(43.67,0.15) v7(43.95,40.41) v7(44.05,38.61) v7(44.13,38.28) v7(44.25,40.41) v7(44.52,7.47) v7(44.52,6.56) v7(44.52,5.64) v7(44.52,4.73) v7(44.52,3.81) v7(44.52,1.99) v7(44.52,1.07) v7(44.52,0.16) v7(44.56,40.41) v7(44.86,40.41) v7(44.89,36.93) v7(45.17,40.41) v7(45.47,40.41) v7(45.63,36.93) v7(45.78,40.41) v7(46.08,40.41) v7(46.06,36.93) v7(46.26,37.92) v7(46.39,40.41) v7(46.59,37.97) v7(46.69,40.41) v7(46.67,38.71) v7(46.74,38.3) v7(47.15,36.91) v7(49.82,38.46) v7(49.82,38.1) v7(50.1,37.39) v7(50.1,37.08) v7(50.1,36.75) v7(50.1,36.45) v7(50.12,36.14) v7(50.17,38.46) v7(50.17,38.1) v7(50.17,35.84) v7(50.4,37.52) v7(50.4,37.19) v7(50.4,36.86) v7(50.43,36.53) v7(50.45,36.2) v7(50.48,35.86) v7(50.71,36.86) v7(50.83,37.19) v7(50.81,35.92) v7(51.21,41.4) v7(51.52,41.4) v7(51.82,41.4) v7(52.13,42.39) v7(52.13,41.4) v7(52.43,42.39) v7(52.43,41.4) v7(52.46,7.48) v7(52.46,6.57) v7(52.46,5.65) v7(52.46,4.74) v7(52.46,3.82) v7(52.46,2) v7(52.46,1.08) v7(52.46,0.17) v7(52.74,42.39) v7(52.74,41.4) v7(53.04,43.51) v7(53.04,42.39) v7(53.04,41.4) v7(53.32,43.59) v7(53.32,7.47) v7(53.32,6.55) v7(53.32,5.64) v7(53.32,4.72) v7(53.32,1.07) v7(53.32,0.15) v7(53.35,42.39) v7(53.63,43.69) v7(53.65,42.39) v7(53.91,43.79) v7(53.96,42.39) v7(54.19,43.92) v7(54.24,7.47) v7(54.24,6.55) v7(54.24,5.64) v7(54.24,4.72) v7(54.24,1.07) v7(54.24,0.15) v7(55.15,7.46) v7(55.15,6.55) v7(55.15,5.64) v7(55.15,4.72) v7(55.15,3.81) v7(55.15,1.98) v7(55.15,1.06) v7(55.15,0.15) v7(56.07,7.47) v7(56.07,6.55) v7(56.07,5.64) v7(56.07,4.72) v7(56.07,3.81) v7(56.07,2.89) v7(56.07,1.98) v7(56.07,1.07) v7(56.07,0.15) v7(56.98,7.47) v7(56.98,6.55) v7(56.98,5.64) v7(56.98,4.72) v7(56.98,3.81) v7(56.98,2.9) v7(56.98,1.98) v7(56.98,1.07) v7(56.98,0.15) v7(57.59,7.47) v7(57.59,7.16) v7(57.59,6.86) v7(57.59,6.55) v7(57.59,6.25) v7(57.59,5.94) v7(57.59,5.64) v7(57.59,5.33) v7(57.59,5.03) v7(57.59,4.72) v7(57.59,4.42) v7(57.59,4.11) v7(57.59,3.81) v7(57.59,3.5) v7(57.59,3.2) v7(57.59,2.89) v7(57.59,2.59) v7(57.59,2.29) v7(57.59,1.98) v7(57.59,1.68) v7(57.59,1.37) v7(57.59,1.07) v7(57.59,0.76) v7(57.59,0.46) v7(57.59,0.15) v7(57.91,7.65) v7(58.01,0.46) v7(58.01,0.15) v7(58.09,3.51) v7(58.09,1.07) v7(58.09,0.76) v7(58.15,7.46) v7(58.15,7.15) v7(58.15,6.84) v7(58.15,6.54) v7(58.15,6.23) v7(58.15,5.93) v7(58.15,5.63) v7(58.15,5.32) v7(58.15,5.02) v7(58.15,4.71) v7(58.15,4.41) v7(58.15,4.1) v7(58.16,3.8) v7(58.16,3.22) v7(58.2,2.89) v7(58.2,2.59) v7(58.2,2.28) v7(58.2,1.98) v7(58.2,1.67) v7(58.2,1.37) v7(59.12,2.9) v7(59.12,2.59) v7(59.12,2.28) v7(59.12,1.98) v7(59.12,1.67) v7(59.12,1.37) v7(59.17,7.45) v7(59.16,7.15) v7(59.16,6.84) v7(59.16,6.54) v7(59.16,6.23) v7(59.16,5.93) v7(59.16,5.63) v7(59.16,5.32) v7(59.16,5.02) v7(59.16,4.71) v7(59.16,4.41) v7(59.16,4.1) v7(59.16,3.8) v7(59.23,3.5) v7(59.15,3.22) v7(59.23,1.07) v7(59.23,0.76) v7(59.3,0.46) v7(59.3,0.15) v7(59.41,7.65) v7(59.72,7.47) v7(59.72,7.16) v7(59.72,6.86) v7(59.72,6.55) v7(59.72,6.25) v7(59.72,5.94) v7(59.72,5.64) v7(59.72,5.33) v7(59.72,5.03) v7(59.72,4.72) v7(59.72,4.42) v7(59.72,4.11) v7(59.72,3.81) v7(59.72,3.5) v7(59.72,3.2) v7(59.72,2.89) v7(59.72,2.59) v7(59.72,2.28) v7(59.72,1.98) v7(59.72,1.68) v7(59.72,1.37) v7(59.72,1.07) v7(59.72,0.76) v7(59.72,0.46) v7(59.72,0.15) v7(60.33,7.47) v7(60.33,6.55) v7(60.33,5.64) v7(60.33,4.72) v7(60.33,3.81) v7(60.33,2.89) v7(60.33,1.98) v7(60.33,1.07) v7(60.33,0.15) v7(61.25,7.47) v7(61.25,6.55) v7(61.25,5.64) v7(61.25,4.72) v7(61.25,3.81) v7(61.25,2.89) v7(61.25,1.98) v7(61.25,1.07) v7(61.25,0.15) v7(62.16,7.47) v7(62.16,6.55) v7(62.16,5.64) v7(62.16,4.72) v7(62.16,3.81) v7(62.16,1.98) v7(62.16,1.06) v7(62.16,0.15) v7(63.08,7.46) v7(63.08,6.55) v7(63.08,5.64) v7(63.08,4.72) v7(63.08,1.07) v7(63.08,0.15) v7(63.99,7.47) v7(63.99,6.55) v7(63.99,5.64) v7(63.99,4.72) v7(63.99,1.07) v7(63.99,0.15) v7(64.84,7.47) v7(64.84,6.56) v7(64.84,5.64) v7(64.84,4.73) v7(64.84,3.81) v7(64.84,1.99) v7(64.84,1.07) v7(64.84,0.16) v7(82.31,67.96) v7(82.31,66.65) v7(82.31,16.16) v7(82.3,14.82) v7(82.55,73.5) v7(82.56,72.64) v7(82.56,71.73) v7(82.56,70.82) v7(82.56,69.9) v7(82.56,68.99) v7(82.56,68.38) v7(82.57,67.8) v7(82.57,66.8) v7(82.56,66.24) v7(82.56,65.63) v7(82.56,64.72) v7(82.56,63.81) v7(82.56,62.89) v7(82.56,61.97) v7(82.55,61.11) v7(82.55,21.68) v7(82.56,20.83) v7(82.56,19.91) v7(82.56,19) v7(82.56,18.08) v7(82.56,17.17) v7(82.56,16.56) v7(82.57,16.01) v7(82.56,14.98) v7(82.56,14.43) v7(82.56,13.82) v7(82.56,12.9) v7(82.56,11.99) v7(82.56,11.07) v7(82.56,10.16) v7(82.55,9.3) v7(82.86,68.38) v7(82.88,67.82) v7(82.88,66.8) v7(82.86,66.24) v7(82.86,16.56) v7(82.88,16) v7(82.87,14.98) v7(82.86,14.43) v7(83.17,68.38) v7(83.18,67.82) v7(83.18,66.8) v7(83.17,66.24) v7(83.17,16.56) v7(83.18,16) v7(83.18,14.99) v7(83.17,14.43) v7(83.47,73.5) v7(83.47,72.64) v7(83.48,71.73) v7(83.47,70.82) v7(83.47,69.9) v7(83.47,68.99) v7(83.47,68.38) v7(83.49,67.82) v7(83.49,66.8) v7(83.47,66.24) v7(83.47,65.63) v7(83.47,64.72) v7(83.47,63.8) v7(83.47,62.89) v7(83.47,61.97) v7(83.46,61.12) v7(83.47,21.68) v7(83.47,20.83) v7(83.48,19.91) v7(83.47,19) v7(83.47,18.08) v7(83.47,17.17) v7(83.47,16.56) v7(83.49,16) v7(83.49,14.98) v7(83.47,14.43) v7(83.47,13.82) v7(83.47,12.9) v7(83.47,11.99) v7(83.47,11.07) v7(83.47,10.16) v7(83.46,9.3) v7(83.78,68.38) v7(83.79,67.82) v7(83.79,66.8) v7(83.78,66.24) v7(83.78,16.56) v7(83.79,16) v7(83.79,14.99) v7(83.78,14.43) v7(84.08,68.38) v7(84.1,67.82) v7(84.1,66.8) v7(84.08,66.24) v7(84.08,16.56) v7(84.1,16) v7(84.1,14.99) v7(84.08,14.43) v7(84.38,73.5) v7(84.39,72.64) v7(84.39,71.73) v7(84.39,70.82) v7(84.39,69.9) v7(84.39,68.99) v7(84.39,68.38) v7(84.4,67.82) v7(84.4,66.8) v7(84.39,66.24) v7(84.39,65.63) v7(84.39,64.72) v7(84.39,63.8) v7(84.39,62.89) v7(84.39,61.97) v7(84.37,61.12) v7(84.38,21.68) v7(84.39,20.83) v7(84.39,19.91) v7(84.39,19) v7(84.39,18.08) v7(84.39,17.17) v7(84.39,16.56) v7(84.4,16) v7(84.4,14.99) v7(84.39,14.43) v7(84.39,13.82) v7(84.39,12.9) v7(84.39,11.99) v7(84.39,11.07) v7(84.39,10.16) v7(84.37,9.3) v7(84.69,68.38) v7(84.71,67.82) v7(84.71,66.8) v7(84.69,66.24) v7(84.69,16.56) v7(84.71,16) v7(84.71,14.99) v7(84.69,14.43) v7(85,68.38) v7(85.01,67.82) v7(85.01,66.8) v7(85,66.24) v7(85,16.56) v7(85.01,16) v7(85.01,14.99) v7(85,14.43) v7(85.3,73.5) v7(85.3,72.64) v7(85.3,71.73) v7(85.3,70.82) v7(85.3,69.9) v7(85.3,68.99) v7(85.3,68.38) v7(85.31,67.82) v7(85.31,66.8) v7(85.3,66.24) v7(85.3,65.63) v7(85.3,64.72) v7(85.3,63.8) v7(85.3,62.89) v7(85.3,61.97) v7(85.29,61.12) v7(85.3,21.68) v7(85.3,20.83) v7(85.3,19.91) v7(85.3,19) v7(85.3,18.08) v7(85.3,17.17) v7(85.3,16.56) v7(85.31,16) v7(85.31,14.99) v7(85.3,14.43) v7(85.3,13.82) v7(85.3,12.9) v7(85.3,11.99) v7(85.3,11.07) v7(85.3,10.16) v7(85.29,9.3) v7(85.61,68.38) v7(85.62,67.82) v7(85.62,66.8) v7(85.61,66.24) v7(85.61,16.56) v7(85.62,16) v7(85.62,14.99) v7(85.61,14.43) v7(85.91,68.38) v7(85.92,67.82) v7(85.92,66.8) v7(85.91,66.24) v7(85.91,16.56) v7(85.92,16) v7(85.92,14.99) v7(85.91,14.43) v7(86.21,73.5) v7(86.22,70.82) v7(86.22,69.9) v7(86.22,68.99) v7(86.22,68.38) v7(86.23,67.82) v7(86.24,66.81) v7(86.22,66.24) v7(86.22,65.63) v7(86.22,64.72) v7(86.22,63.8) v7(86.2,61.12) v7(86.21,21.68) v7(86.22,19) v7(86.22,18.08) v7(86.22,17.17) v7(86.22,16.56) v7(86.22,16) v7(86.24,15) v7(86.22,14.43) v7(86.22,13.82) v7(86.22,12.9) v7(86.22,11.99) v7(86.2,9.3) v7(86.52,68.38) v7(86.52,67.88) v7(86.52,66.74) v7(86.52,66.24) v7(86.52,16.56) v7(86.52,16.07) v7(86.52,14.92) v7(86.52,14.43) v7(86.83,68.38) v7(86.81,67.8) v7(86.81,66.82) v7(86.83,66.24) v7(86.83,16.56) v7(86.81,15.99) v7(86.81,15) v7(86.83,14.43) v7(87.13,69.9) v7(87.13,68.99) v7(87.13,68.38) v7(87.13,67.77) v7(87.13,66.85) v7(87.13,66.24) v7(87.13,65.63) v7(87.13,64.72) v7(87.13,18.08) v7(87.13,17.17) v7(87.13,16.56) v7(87.12,15.96) v7(87.13,15.04) v7(87.13,14.43) v7(87.13,13.82) v7(87.13,12.9) v7(87.44,68.38) v7(87.44,67.77) v7(87.44,66.85) v7(87.44,66.24) v7(87.44,16.56) v7(87.44,15.95) v7(87.44,15.04) v7(87.44,14.43) v7(87.74,68.38) v7(87.74,67.77) v7(87.74,66.85) v7(87.74,66.24) v7(87.74,16.56) v7(87.74,15.95) v7(87.74,15.04) v7(87.74,14.43) v7(88.04,73.5) v7(88.05,69.9) v7(88.05,68.99) v7(88.05,68.38) v7(88.05,66.24) v7(88.05,65.63) v7(88.05,64.72) v7(88.04,63.81) v7(88.03,61.12) v7(88.04,21.68) v7(88.05,18.08) v7(88.05,17.17) v7(88.05,16.56) v7(88.05,14.43) v7(88.05,13.82) v7(88.05,12.9) v7(88.04,11.99) v7(88.03,9.3) v7(88.05,70.82) v7(88.05,67.77) v7(88.05,66.85) v7(88.05,19) v7(88.05,15.95) v7(88.05,15.04) v7(88.35,68.38) v7(88.35,67.77) v7(88.35,66.85) v7(88.35,66.24) v7(88.35,16.56) v7(88.35,15.95) v7(88.35,15.04) v7(88.35,14.43) v7(88.66,68.38) v7(88.66,67.77) v7(88.66,66.85) v7(88.66,66.24) v7(88.66,16.56) v7(88.66,15.95) v7(88.66,15.04) v7(88.66,14.43) v7(88.94,61.12) v7(88.94,9.3) v7(88.95,73.5) v7(88.96,72.64) v7(88.96,71.73) v7(88.96,70.82) v7(88.96,69.9) v7(88.96,68.99) v7(88.96,68.38) v7(88.96,67.88) v7(88.96,66.74) v7(88.96,66.24) v7(88.96,65.63) v7(88.96,64.72) v7(88.96,63.81) v7(88.96,62.89) v7(88.96,61.98) v7(88.95,21.68) v7(88.96,20.83) v7(88.96,19.91) v7(88.96,19) v7(88.96,18.08) v7(88.96,17.17) v7(88.96,16.56) v7(88.96,16.07) v7(88.96,14.92) v7(88.96,14.43) v7(88.96,13.82) v7(88.96,12.9) v7(88.96,11.99) v7(88.96,11.08) v7(88.96,10.16) v7(89.26,68.38) v7(89.26,67.88) v7(89.26,66.74) v7(89.26,66.24) v7(89.28,50.71) v7(89.28,49.36) v7(89.29,33.43) v7(89.27,32.08) v7(89.26,16.56) v7(89.26,16.07) v7(89.26,14.92) v7(89.26,14.43) v7(89.52,56.23) v7(89.53,55.37) v7(89.53,54.46) v7(89.53,53.54) v7(89.53,52.63) v7(89.53,51.71) v7(89.53,51.1) v7(89.54,50.55) v7(89.54,49.53) v7(89.53,48.97) v7(89.53,48.36) v7(89.53,47.45) v7(89.53,46.53) v7(89.53,45.62) v7(89.53,44.7) v7(89.52,43.84) v7(89.52,38.95) v7(89.53,38.1) v7(89.53,37.18) v7(89.53,36.27) v7(89.53,35.36) v7(89.53,34.44) v7(89.53,33.83) v7(89.54,33.27) v7(89.53,32.25) v7(89.53,31.7) v7(89.53,31.09) v7(89.53,30.18) v7(89.53,29.26) v7(89.53,28.35) v7(89.53,27.43) v7(89.52,26.57) v7(89.57,68.38) v7(89.57,67.96) v7(89.57,66.66) v7(89.57,66.24) v7(89.57,16.56) v7(89.57,16.14) v7(89.57,14.85) v7(89.57,14.43) v7(89.83,51.11) v7(89.84,50.55) v7(89.84,49.53) v7(89.83,48.97) v7(89.83,33.83) v7(89.84,33.27) v7(89.84,32.26) v7(89.83,31.7) v7(89.87,73.5) v7(89.87,72.65) v7(89.87,71.73) v7(89.87,70.81) v7(89.87,69.9) v7(89.87,68.99) v7(89.87,68.38) v7(89.88,67.96) v7(89.88,66.66) v7(89.87,66.24) v7(89.87,65.63) v7(89.87,64.72) v7(89.87,63.8) v7(89.87,62.89) v7(89.87,61.98) v7(89.86,61.12) v7(89.87,21.68) v7(89.87,20.83) v7(89.87,19.92) v7(89.87,19) v7(89.87,18.08) v7(89.87,17.17) v7(89.87,16.56) v7(89.88,16.14) v7(89.88,14.85) v7(89.87,14.43) v7(89.87,13.82) v7(89.87,12.9) v7(89.87,11.99) v7(89.87,11.07) v7(89.87,10.16) v7(89.86,9.3) v7(90.14,51.11) v7(90.14,48.97) v7(90.14,33.83) v7(90.14,32.25) v7(90.14,31.7) v7(90.15,50.55) v7(90.15,49.53) v7(90.15,33.27) v7(90.44,56.23) v7(90.44,55.37) v7(90.44,54.46) v7(90.44,53.54) v7(90.44,52.63) v7(90.44,51.71) v7(90.44,51.11) v7(90.44,48.97) v7(90.44,48.36) v7(90.44,47.45) v7(90.44,46.53) v7(90.44,45.62) v7(90.44,44.7) v7(90.43,43.85) v7(90.44,38.95) v7(90.44,38.1) v7(90.44,37.18) v7(90.44,36.27) v7(90.44,35.36) v7(90.44,34.44) v7(90.44,33.83) v7(90.44,31.7) v7(90.44,31.09) v7(90.44,30.18) v7(90.44,29.26) v7(90.44,28.35) v7(90.44,27.43) v7(90.43,26.57) v7(90.45,50.55) v7(90.45,49.53) v7(90.45,33.27) v7(90.45,32.25) v7(90.75,51.11) v7(90.75,33.83) v7(90.76,50.55) v7(90.76,49.53) v7(90.75,48.97) v7(90.76,33.27) v7(90.76,32.26) v7(90.75,31.7) v7(91.05,51.11) v7(91.06,50.55) v7(91.06,49.53) v7(91.05,48.97) v7(91.05,33.83) v7(91.06,33.27) v7(91.06,32.26) v7(91.05,31.7) v7(91.34,43.85) v7(91.34,26.57) v7(91.35,56.23) v7(91.35,55.37) v7(91.36,54.46) v7(91.36,53.54) v7(91.36,52.63) v7(91.36,51.71) v7(91.36,51.11) v7(91.37,50.55) v7(91.37,49.53) v7(91.36,48.97) v7(91.36,48.36) v7(91.36,47.45) v7(91.36,46.53) v7(91.36,45.62) v7(91.36,44.7) v7(91.35,38.95) v7(91.35,38.1) v7(91.36,37.18) v7(91.36,36.27) v7(91.36,35.36) v7(91.36,34.44) v7(91.36,33.83) v7(91.37,33.27) v7(91.37,32.26) v7(91.36,31.7) v7(91.36,31.09) v7(91.36,30.18) v7(91.36,29.26) v7(91.36,28.35) v7(91.36,27.43) v7(91.66,51.11) v7(91.67,50.55) v7(91.67,49.53) v7(91.66,48.97) v7(91.66,33.83) v7(91.67,33.27) v7(91.67,32.26) v7(91.66,31.7) v7(91.97,51.11) v7(91.98,50.55) v7(91.98,49.53) v7(91.97,48.97) v7(91.97,33.83) v7(91.98,33.27) v7(91.98,32.26) v7(91.97,31.7) v7(92.26,56.23) v7(92.27,55.37) v7(92.27,54.46) v7(92.27,53.54) v7(92.27,52.63) v7(92.27,51.71) v7(92.27,51.11) v7(92.28,50.55) v7(92.28,49.53) v7(92.27,48.97) v7(92.27,48.36) v7(92.27,47.45) v7(92.27,46.53) v7(92.27,45.62) v7(92.27,44.7) v7(92.25,43.85) v7(92.26,38.95) v7(92.27,38.1) v7(92.27,37.18) v7(92.27,36.27) v7(92.27,35.36) v7(92.27,34.44) v7(92.27,33.83) v7(92.28,33.27) v7(92.28,32.26) v7(92.27,31.7) v7(92.27,31.09) v7(92.27,30.18) v7(92.27,29.26) v7(92.27,28.35) v7(92.27,27.43) v7(92.25,26.57) v7(92.58,51.11) v7(92.59,50.55) v7(92.59,49.53) v7(92.57,48.97) v7(92.58,33.83) v7(92.59,33.27) v7(92.59,32.26) v7(92.57,31.7) v7(92.88,51.11) v7(92.89,50.55) v7(92.89,49.53) v7(92.88,48.97) v7(92.88,33.83) v7(92.89,33.27) v7(92.89,32.26) v7(92.88,31.7) v7(93.18,56.23) v7(93.18,53.54) v7(93.18,52.63) v7(93.18,51.71) v7(93.18,51.11) v7(93.2,50.55) v7(93.2,49.54) v7(93.18,48.97) v7(93.18,48.36) v7(93.18,47.45) v7(93.18,46.53) v7(93.17,43.85) v7(93.18,38.95) v7(93.18,36.27) v7(93.18,35.36) v7(93.18,34.44) v7(93.18,33.83) v7(93.2,33.27) v7(93.2,32.27) v7(93.18,31.7) v7(93.18,31.09) v7(93.18,30.18) v7(93.18,29.26) v7(93.17,26.57) v7(93.49,51.11) v7(93.49,50.61) v7(93.49,49.47) v7(93.49,48.97) v7(93.49,33.83) v7(93.49,33.34) v7(93.49,32.2) v7(93.49,31.7) v7(93.79,51.11) v7(93.78,50.53) v7(93.78,49.54) v7(93.79,48.97) v7(93.79,33.83) v7(93.78,33.26) v7(93.78,32.27) v7(93.79,31.7) v7(94.1,52.63) v7(94.1,51.71) v7(94.1,51.11) v7(94.09,50.5) v7(94.1,49.58) v7(94.1,48.97) v7(94.1,48.36) v7(94.1,47.45) v7(94.1,35.36) v7(94.1,34.44) v7(94.1,33.83) v7(94.09,33.22) v7(94.1,32.31) v7(94.1,31.7) v7(94.1,31.09) v7(94.1,30.18) v7(94.4,51.11) v7(94.4,50.5) v7(94.41,49.58) v7(94.4,48.97) v7(94.4,33.83) v7(94.4,33.22) v7(94.41,32.31) v7(94.4,31.7) v7(94.71,51.11) v7(94.71,50.5) v7(94.71,49.58) v7(94.71,48.97) v7(94.71,33.83) v7(94.71,33.22) v7(94.71,32.31) v7(94.71,31.7) v7(95.01,56.23) v7(95.02,53.55) v7(95.01,52.63) v7(95.01,51.71) v7(95.01,51.11) v7(95.01,50.5) v7(95.01,49.58) v7(95.01,48.97) v7(95.01,48.36) v7(95.01,47.45) v7(95.01,46.53) v7(95,43.85) v7(95.01,38.95) v7(95.02,36.27) v7(95.01,35.36) v7(95.01,34.44) v7(95.01,33.83) v7(95.01,33.22) v7(95.01,32.31) v7(95.01,31.7) v7(95.01,31.09) v7(95.01,30.18) v7(95.01,29.26) v7(95,26.57) v7(95.32,51.11) v7(95.32,50.5) v7(95.32,49.58) v7(95.32,48.97) v7(95.32,33.83) v7(95.32,33.22) v7(95.32,32.31) v7(95.32,31.7) v7(95.62,51.11) v7(95.62,50.5) v7(95.62,49.58) v7(95.62,48.97) v7(95.62,33.83) v7(95.62,33.22) v7(95.62,32.31) v7(95.62,31.7) v7(95.92,56.23) v7(95.93,55.37) v7(95.93,54.46) v7(95.93,53.54) v7(95.93,52.63) v7(95.93,51.71) v7(95.93,51.11) v7(95.93,50.61) v7(95.93,49.47) v7(95.93,48.97) v7(95.93,48.36) v7(95.93,47.45) v7(95.93,46.53) v7(95.93,45.62) v7(95.93,44.7) v7(95.91,43.85) v7(95.92,38.95) v7(95.93,38.1) v7(95.93,37.19) v7(95.93,36.27) v7(95.93,35.36) v7(95.93,34.44) v7(95.93,33.83) v7(95.93,33.34) v7(95.93,32.19) v7(95.93,31.7) v7(95.93,31.09) v7(95.93,30.18) v7(95.93,29.26) v7(95.93,28.35) v7(95.93,27.43) v7(95.91,26.57) v7(96.23,51.11) v7(96.23,50.61) v7(96.23,49.47) v7(96.23,48.97) v7(96.23,33.83) v7(96.23,33.34) v7(96.23,32.19) v7(96.23,31.7) v7(96.54,51.11) v7(96.54,50.69) v7(96.54,49.39) v7(96.54,48.97) v7(96.54,33.83) v7(96.54,33.41) v7(96.54,32.12) v7(96.54,31.7) v7(96.84,56.23) v7(96.84,55.37) v7(96.84,54.46) v7(96.84,53.54) v7(96.84,52.63) v7(96.84,51.71) v7(96.84,51.11) v7(96.85,50.68) v7(96.84,49.39) v7(96.84,48.97) v7(96.84,48.36) v7(96.84,47.45) v7(96.84,46.53) v7(96.84,45.62) v7(96.84,44.7) v7(96.83,43.85) v7(96.84,38.95) v7(96.84,38.1) v7(96.84,37.19) v7(96.84,36.27) v7(96.84,35.36) v7(96.84,34.44) v7(96.84,33.83) v7(96.85,33.41) v7(96.84,32.12) v7(96.84,31.7) v7(96.84,31.09) v7(96.84,30.18) v7(96.84,29.26) v7(96.84,28.35) v7(96.84,27.43) v7(96.83,26.57)
